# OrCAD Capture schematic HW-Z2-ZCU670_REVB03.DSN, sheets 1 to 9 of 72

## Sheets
1 001 Title Page
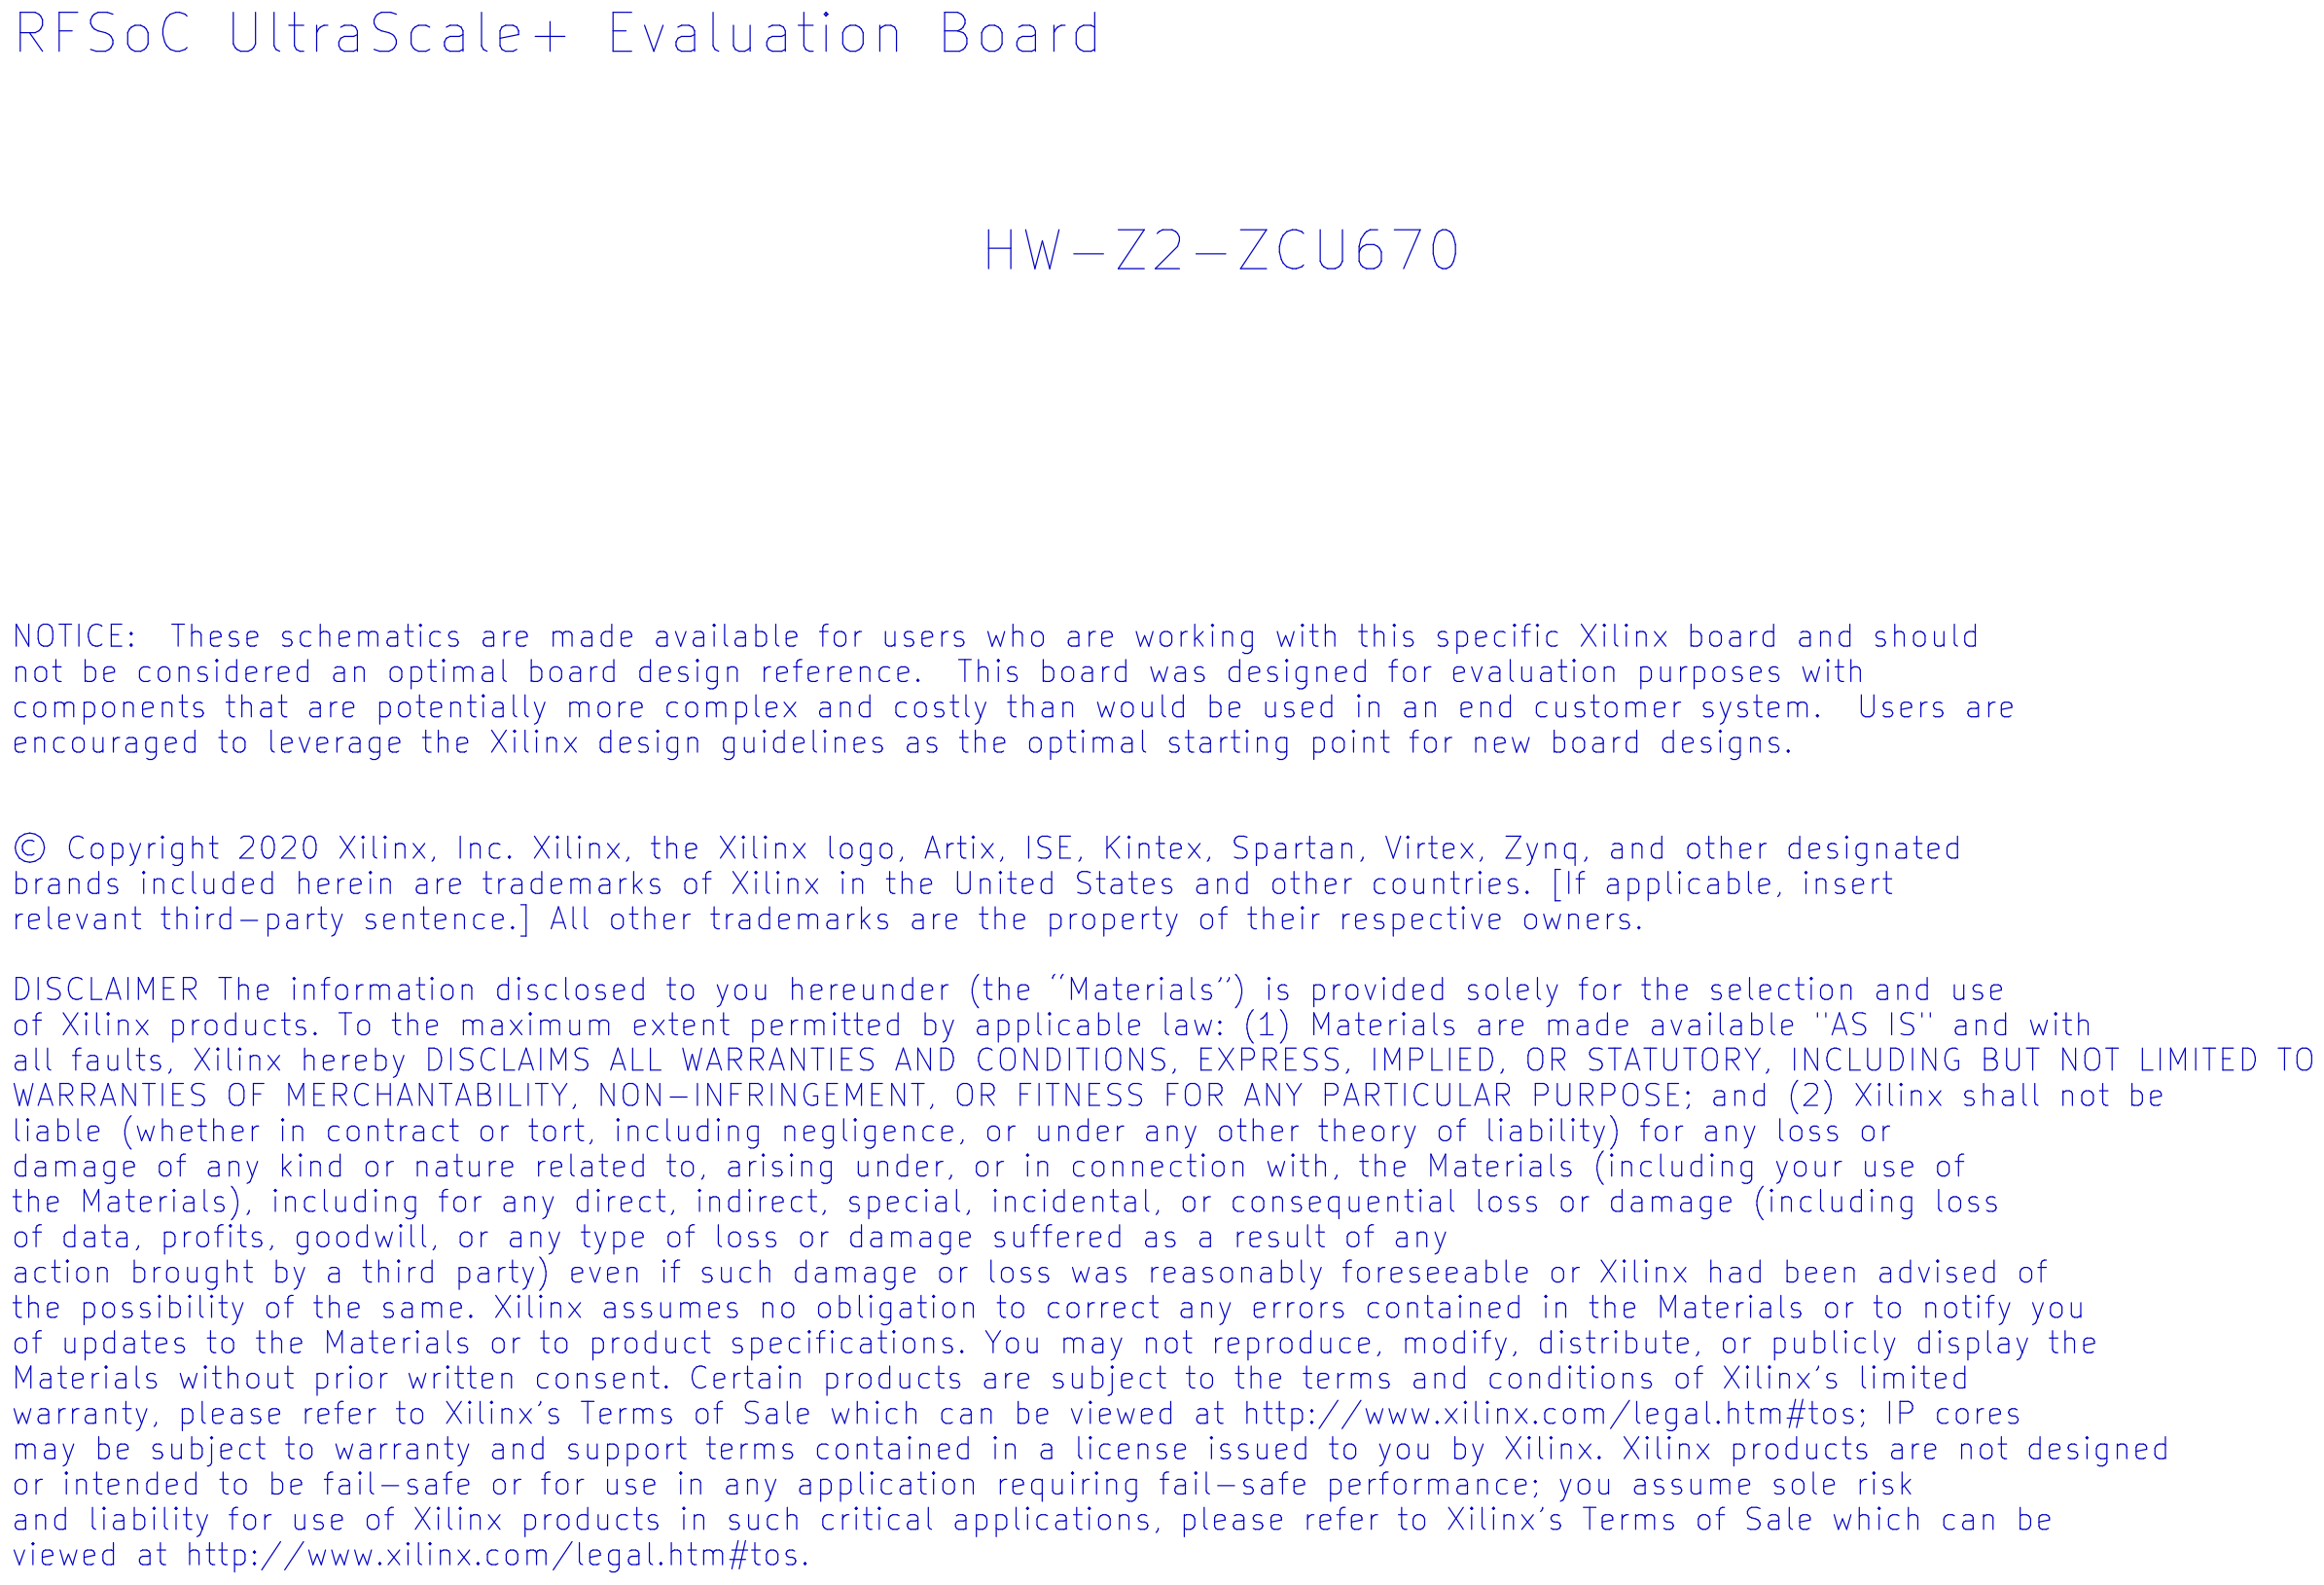
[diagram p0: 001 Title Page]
2 002 Block Diagram
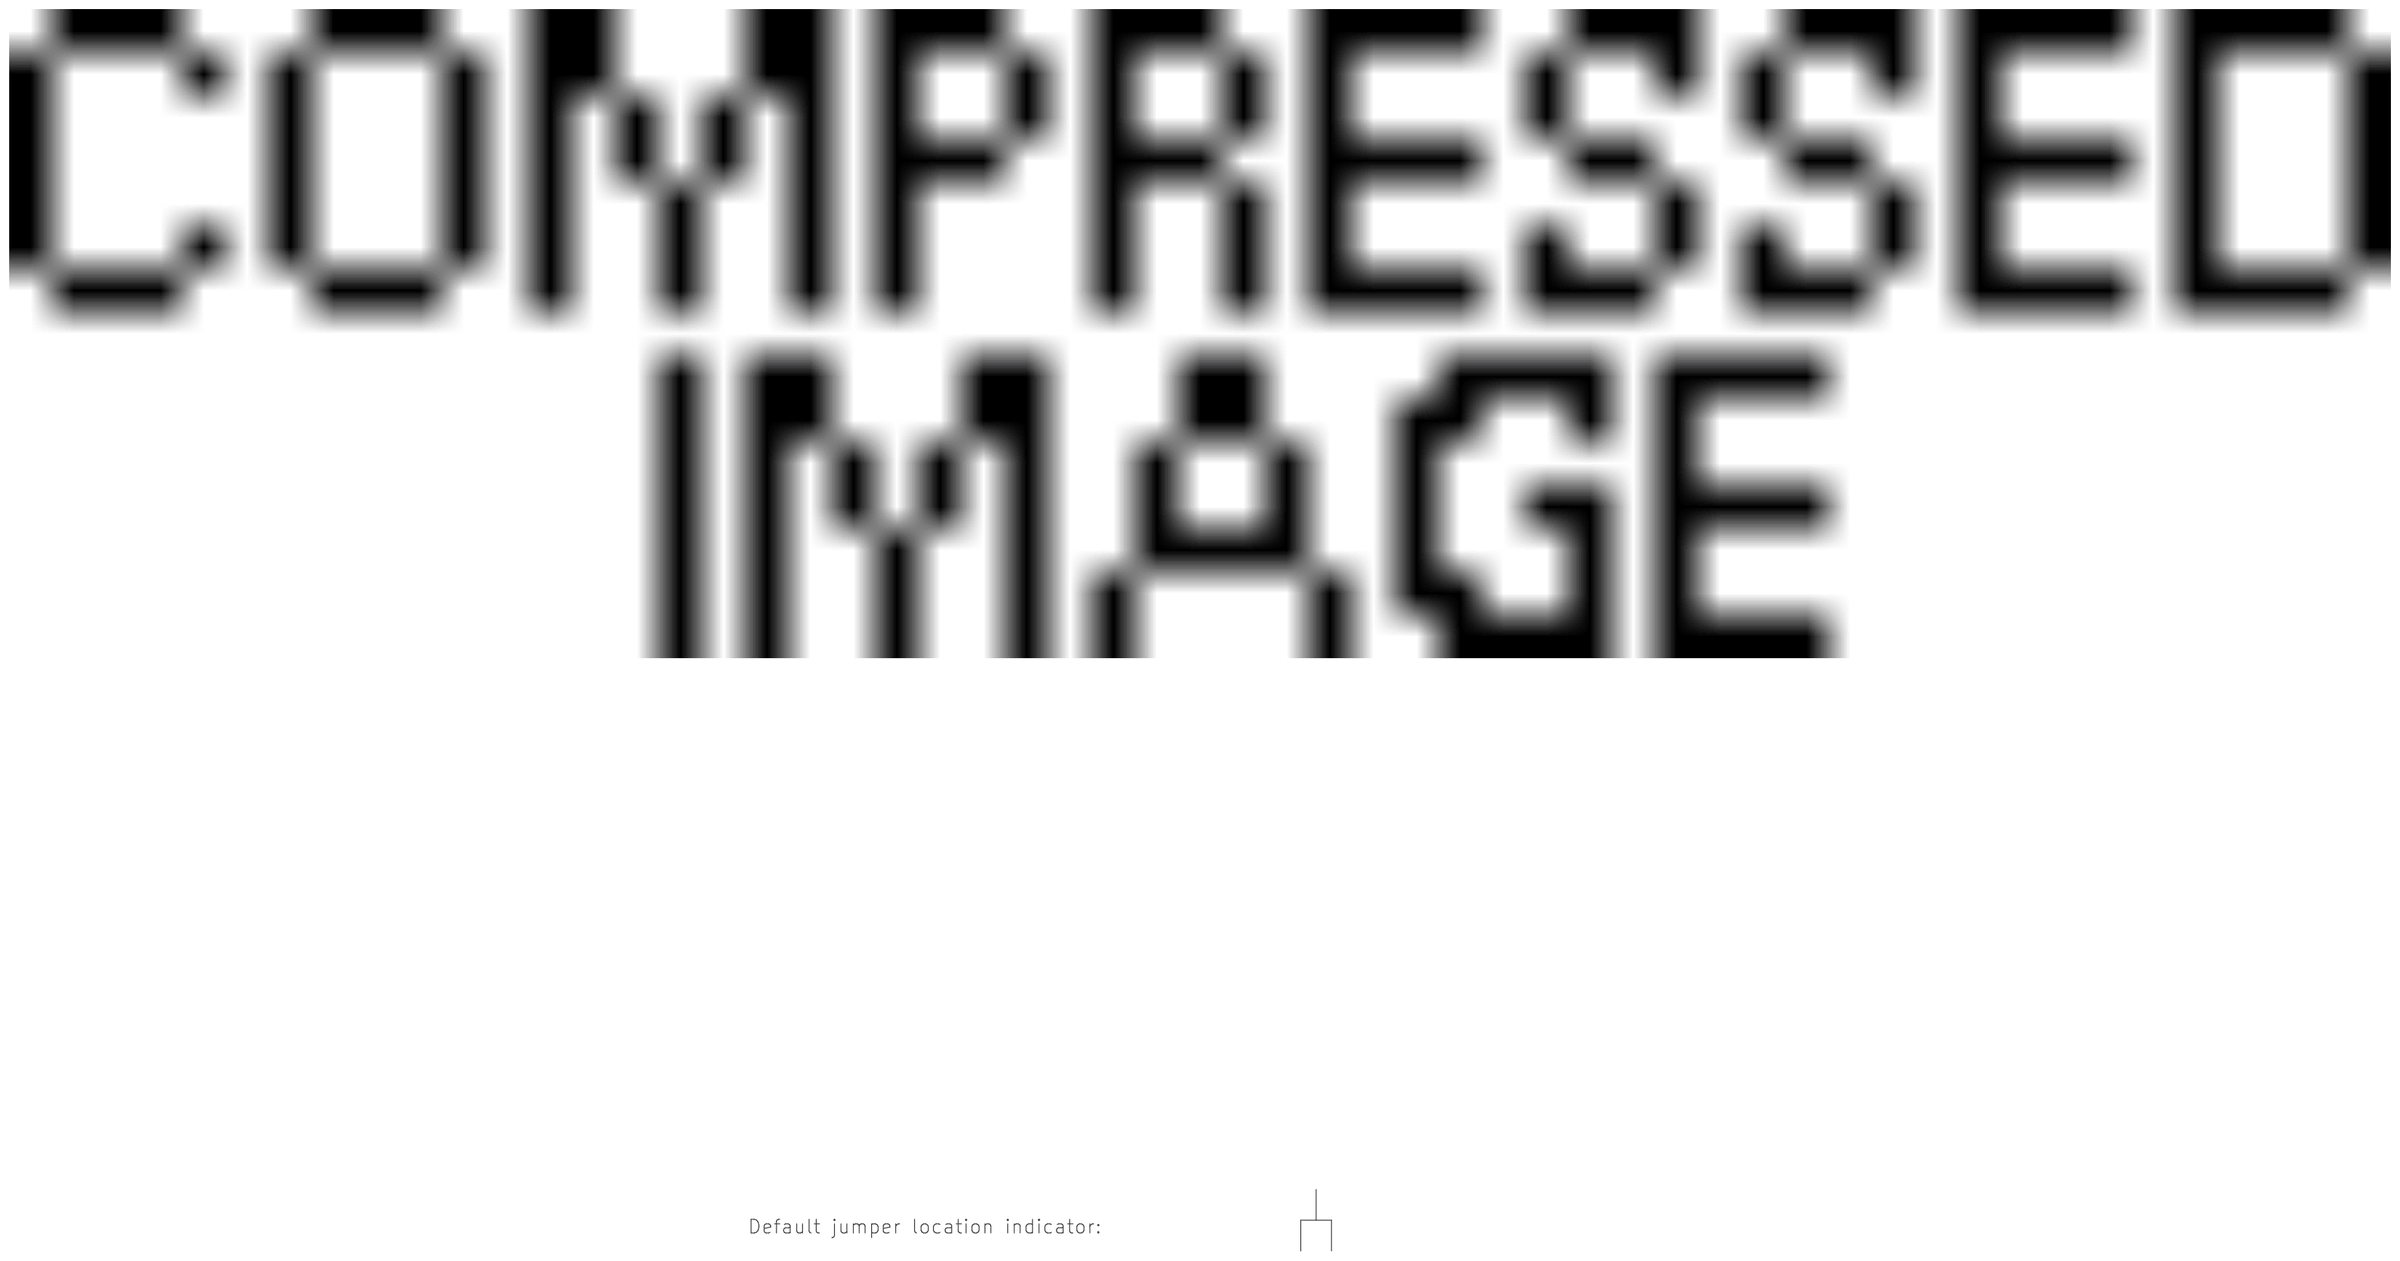
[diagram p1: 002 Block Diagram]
3 003 Zynq Bank 0: size Custom
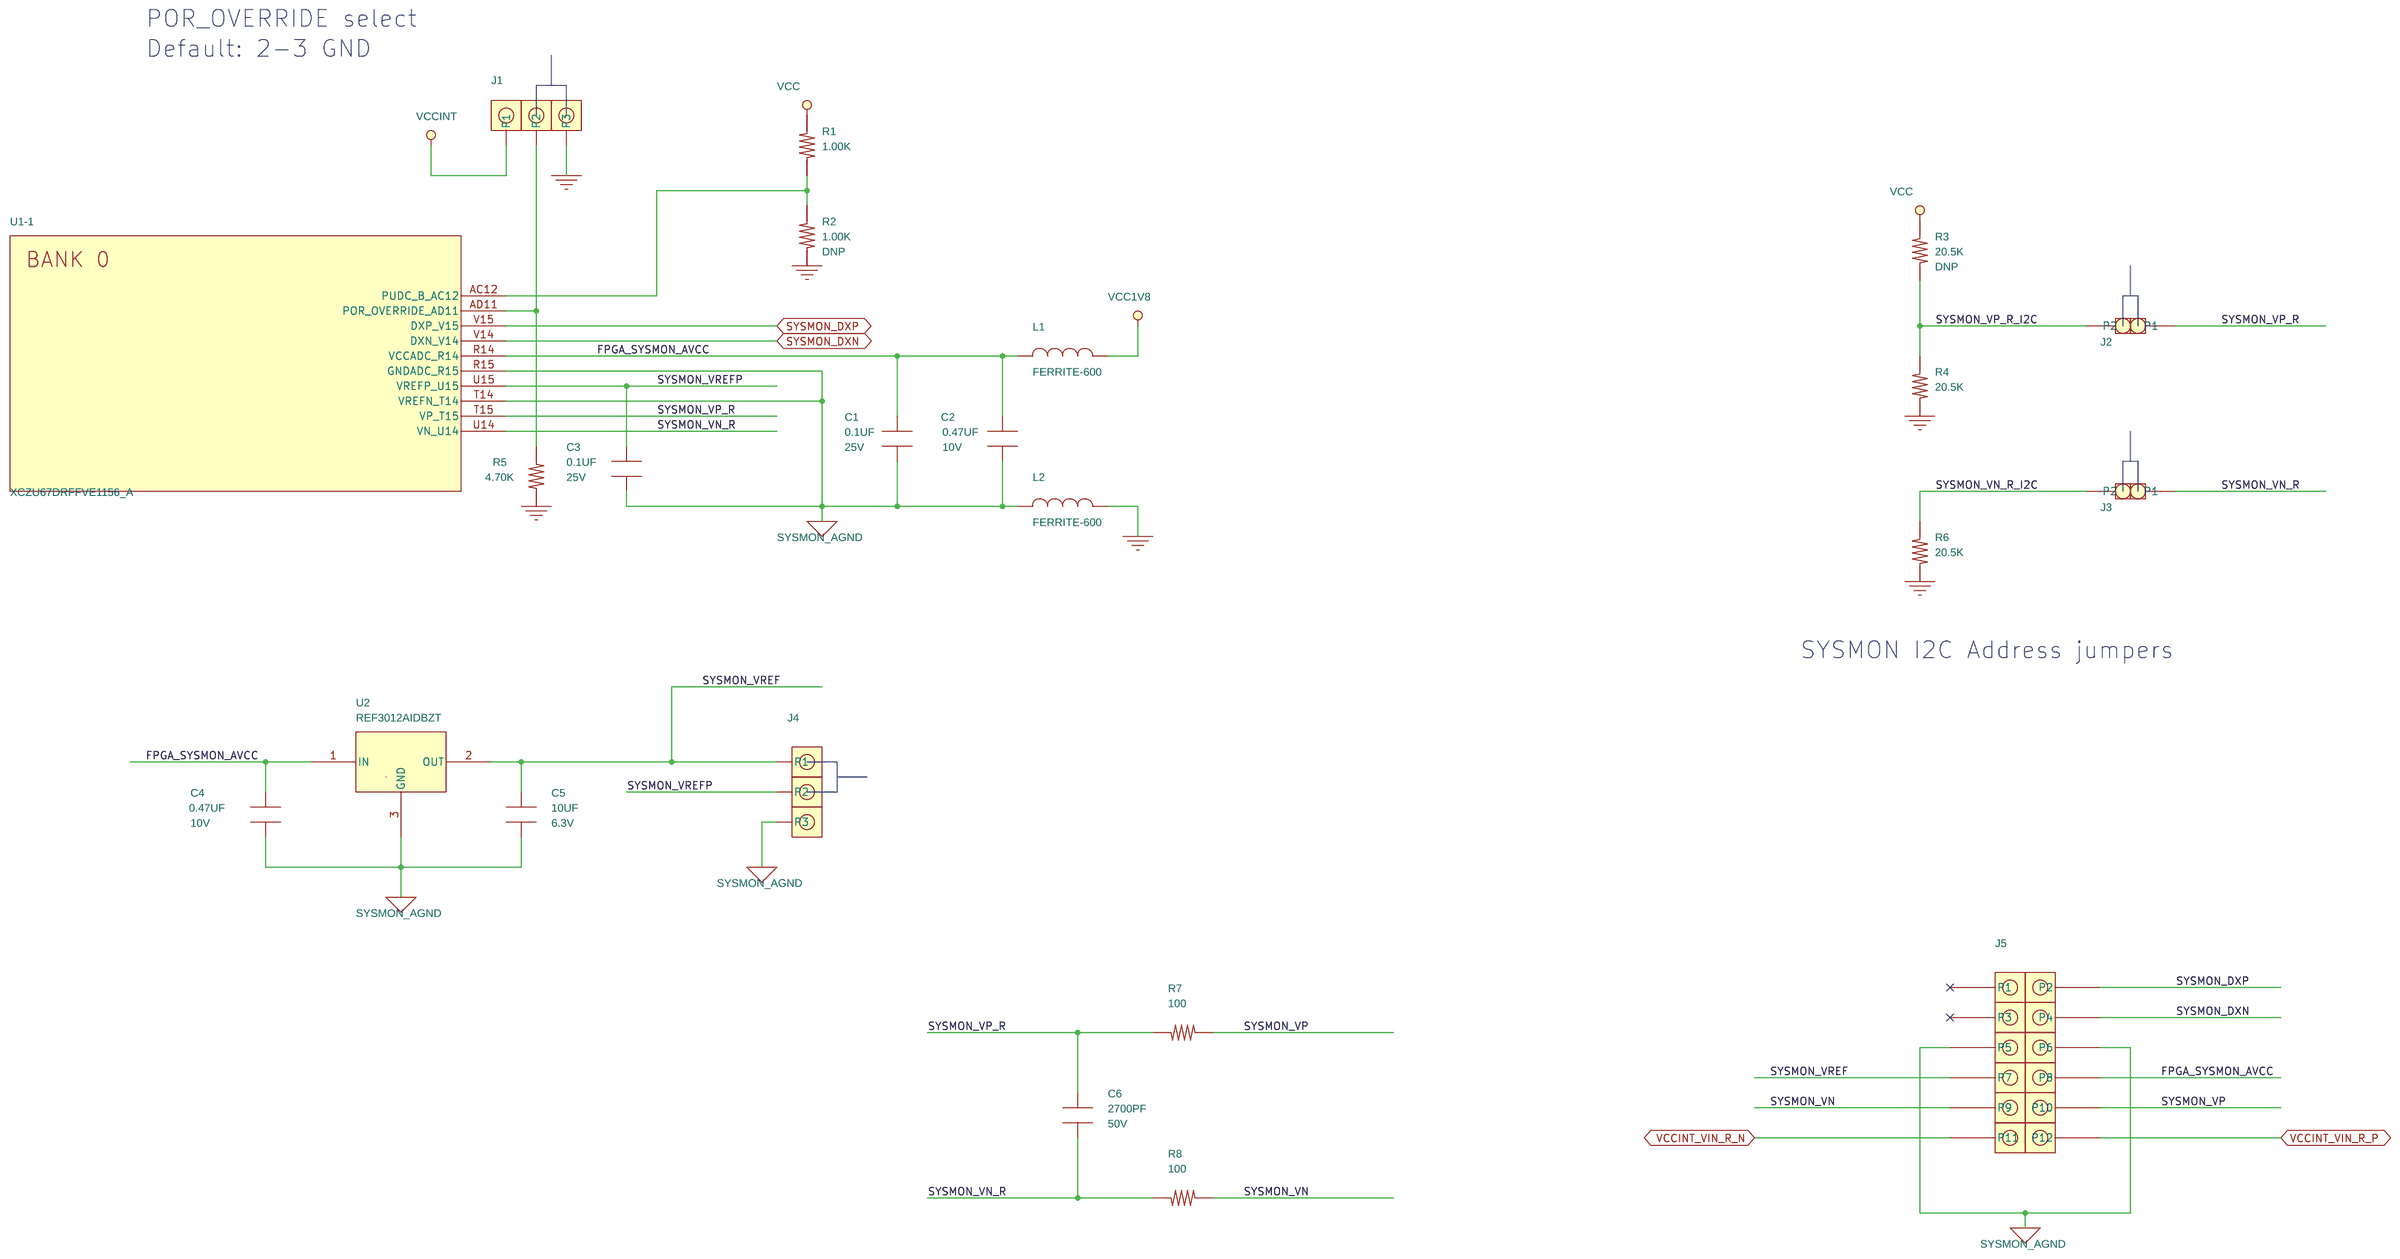
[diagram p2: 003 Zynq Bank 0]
4 004 Zynq Bank 65 66: size Custom
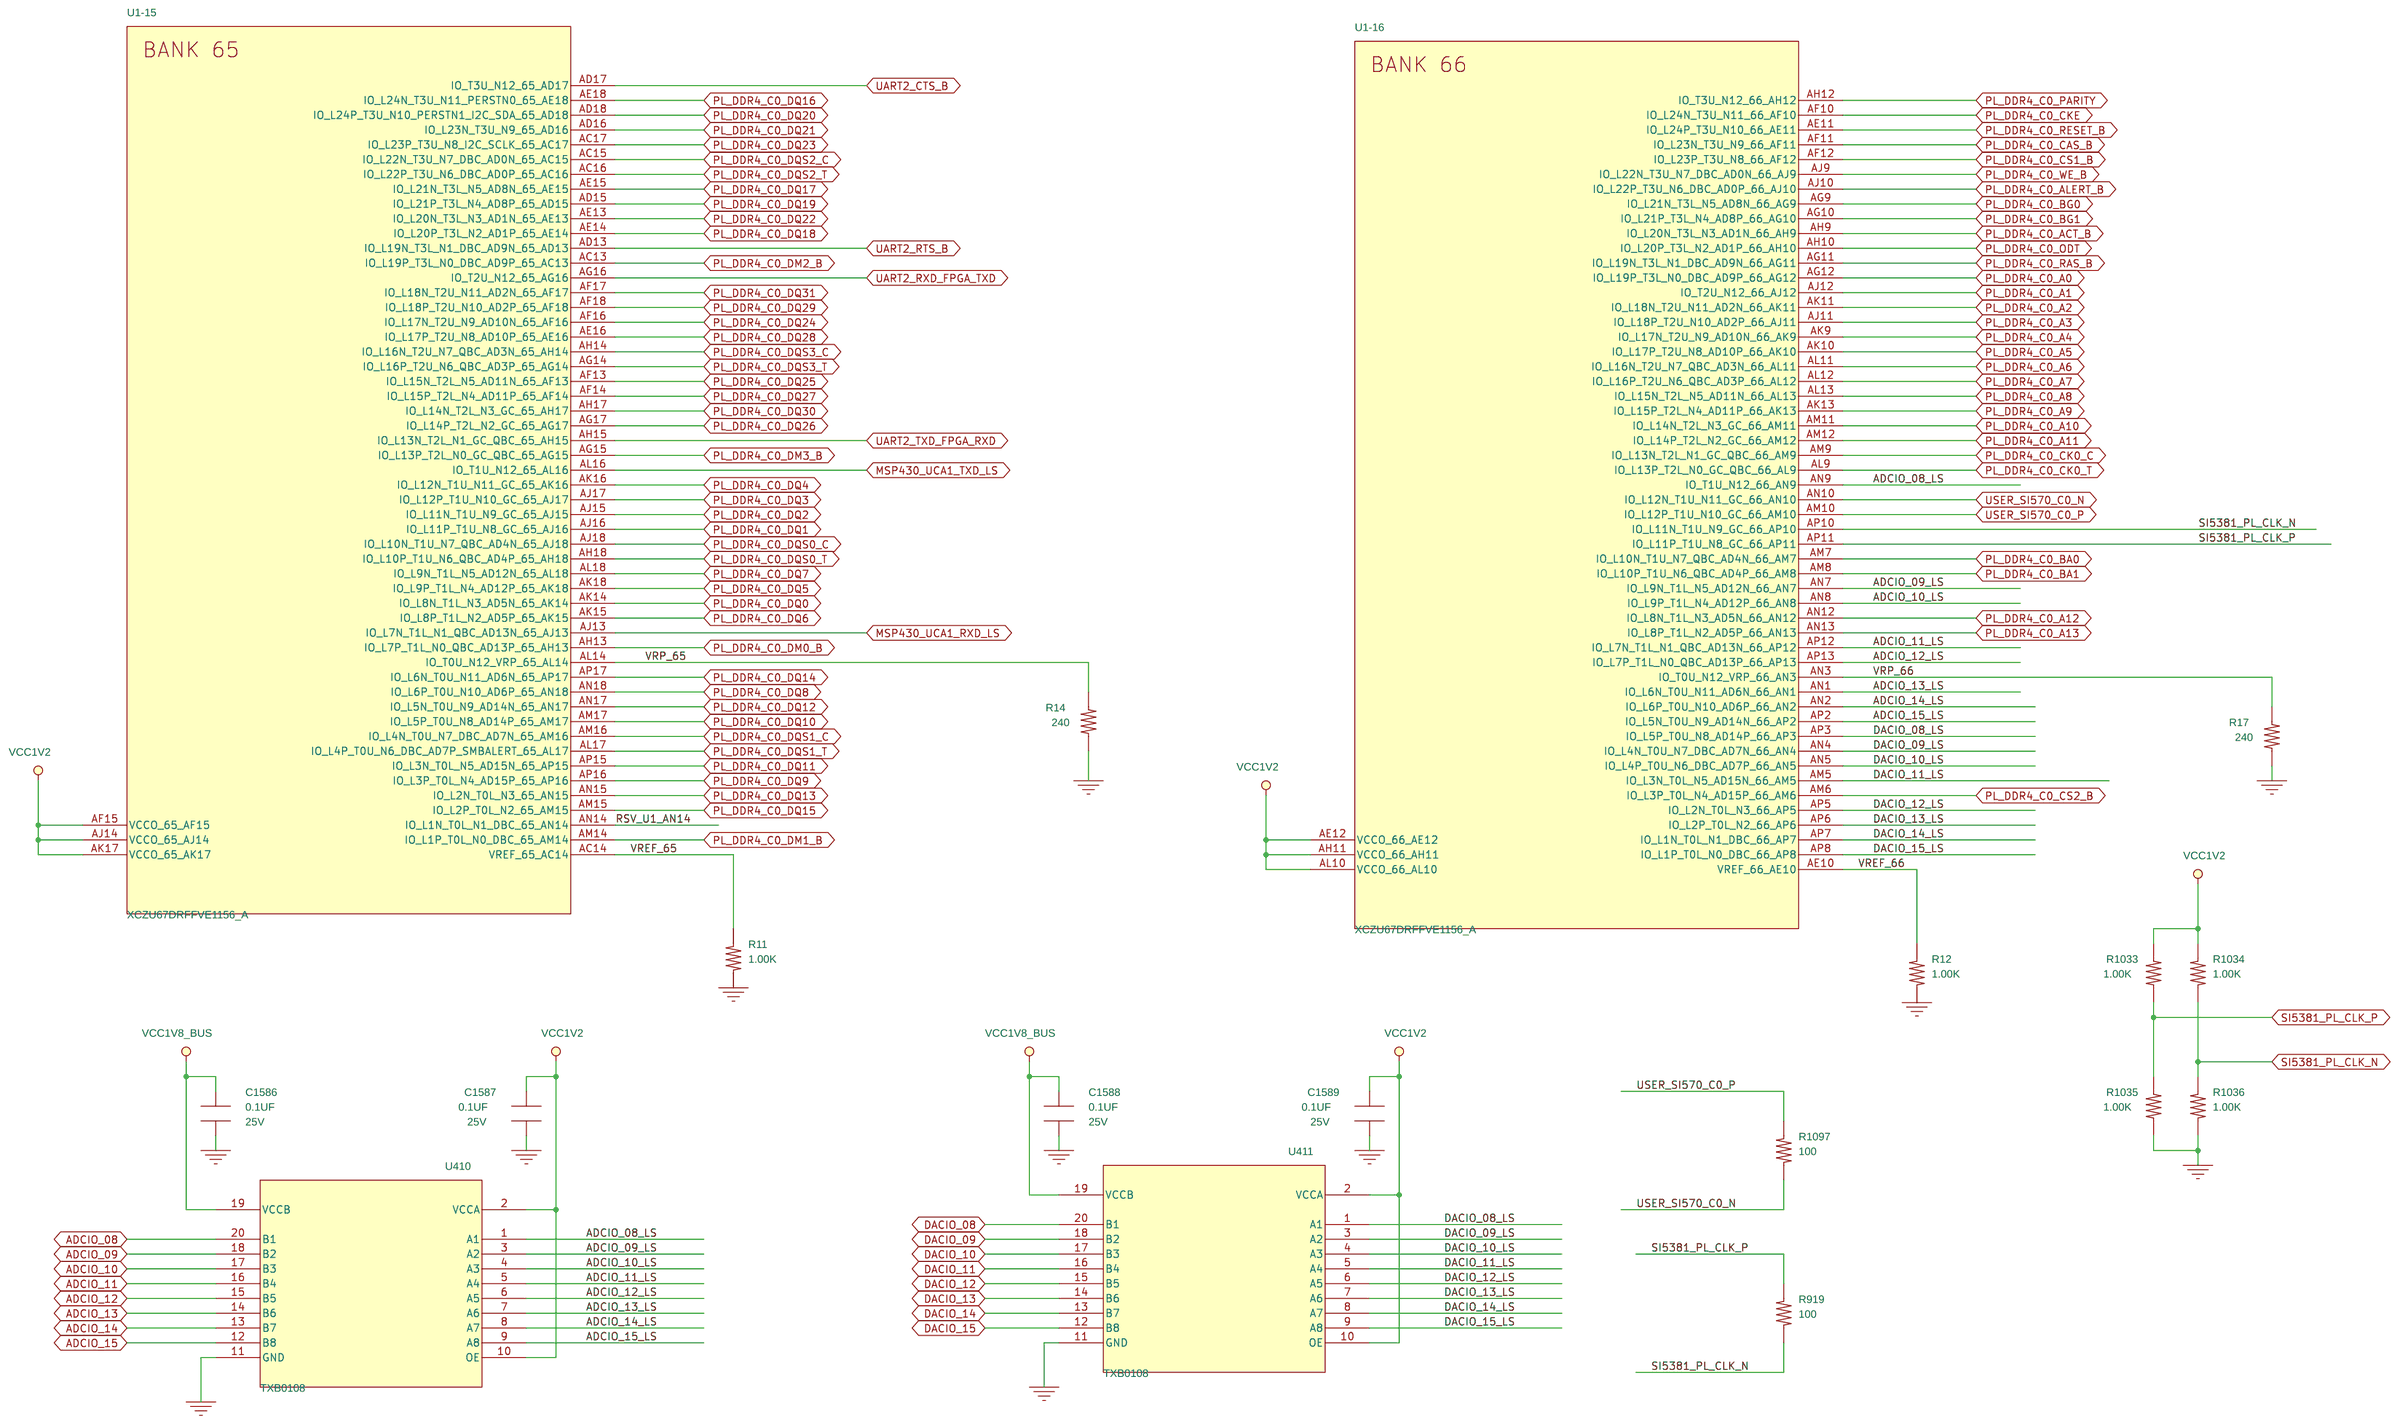
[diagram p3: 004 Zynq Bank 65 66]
5 005 Zynq Bank 67 88: size Custom
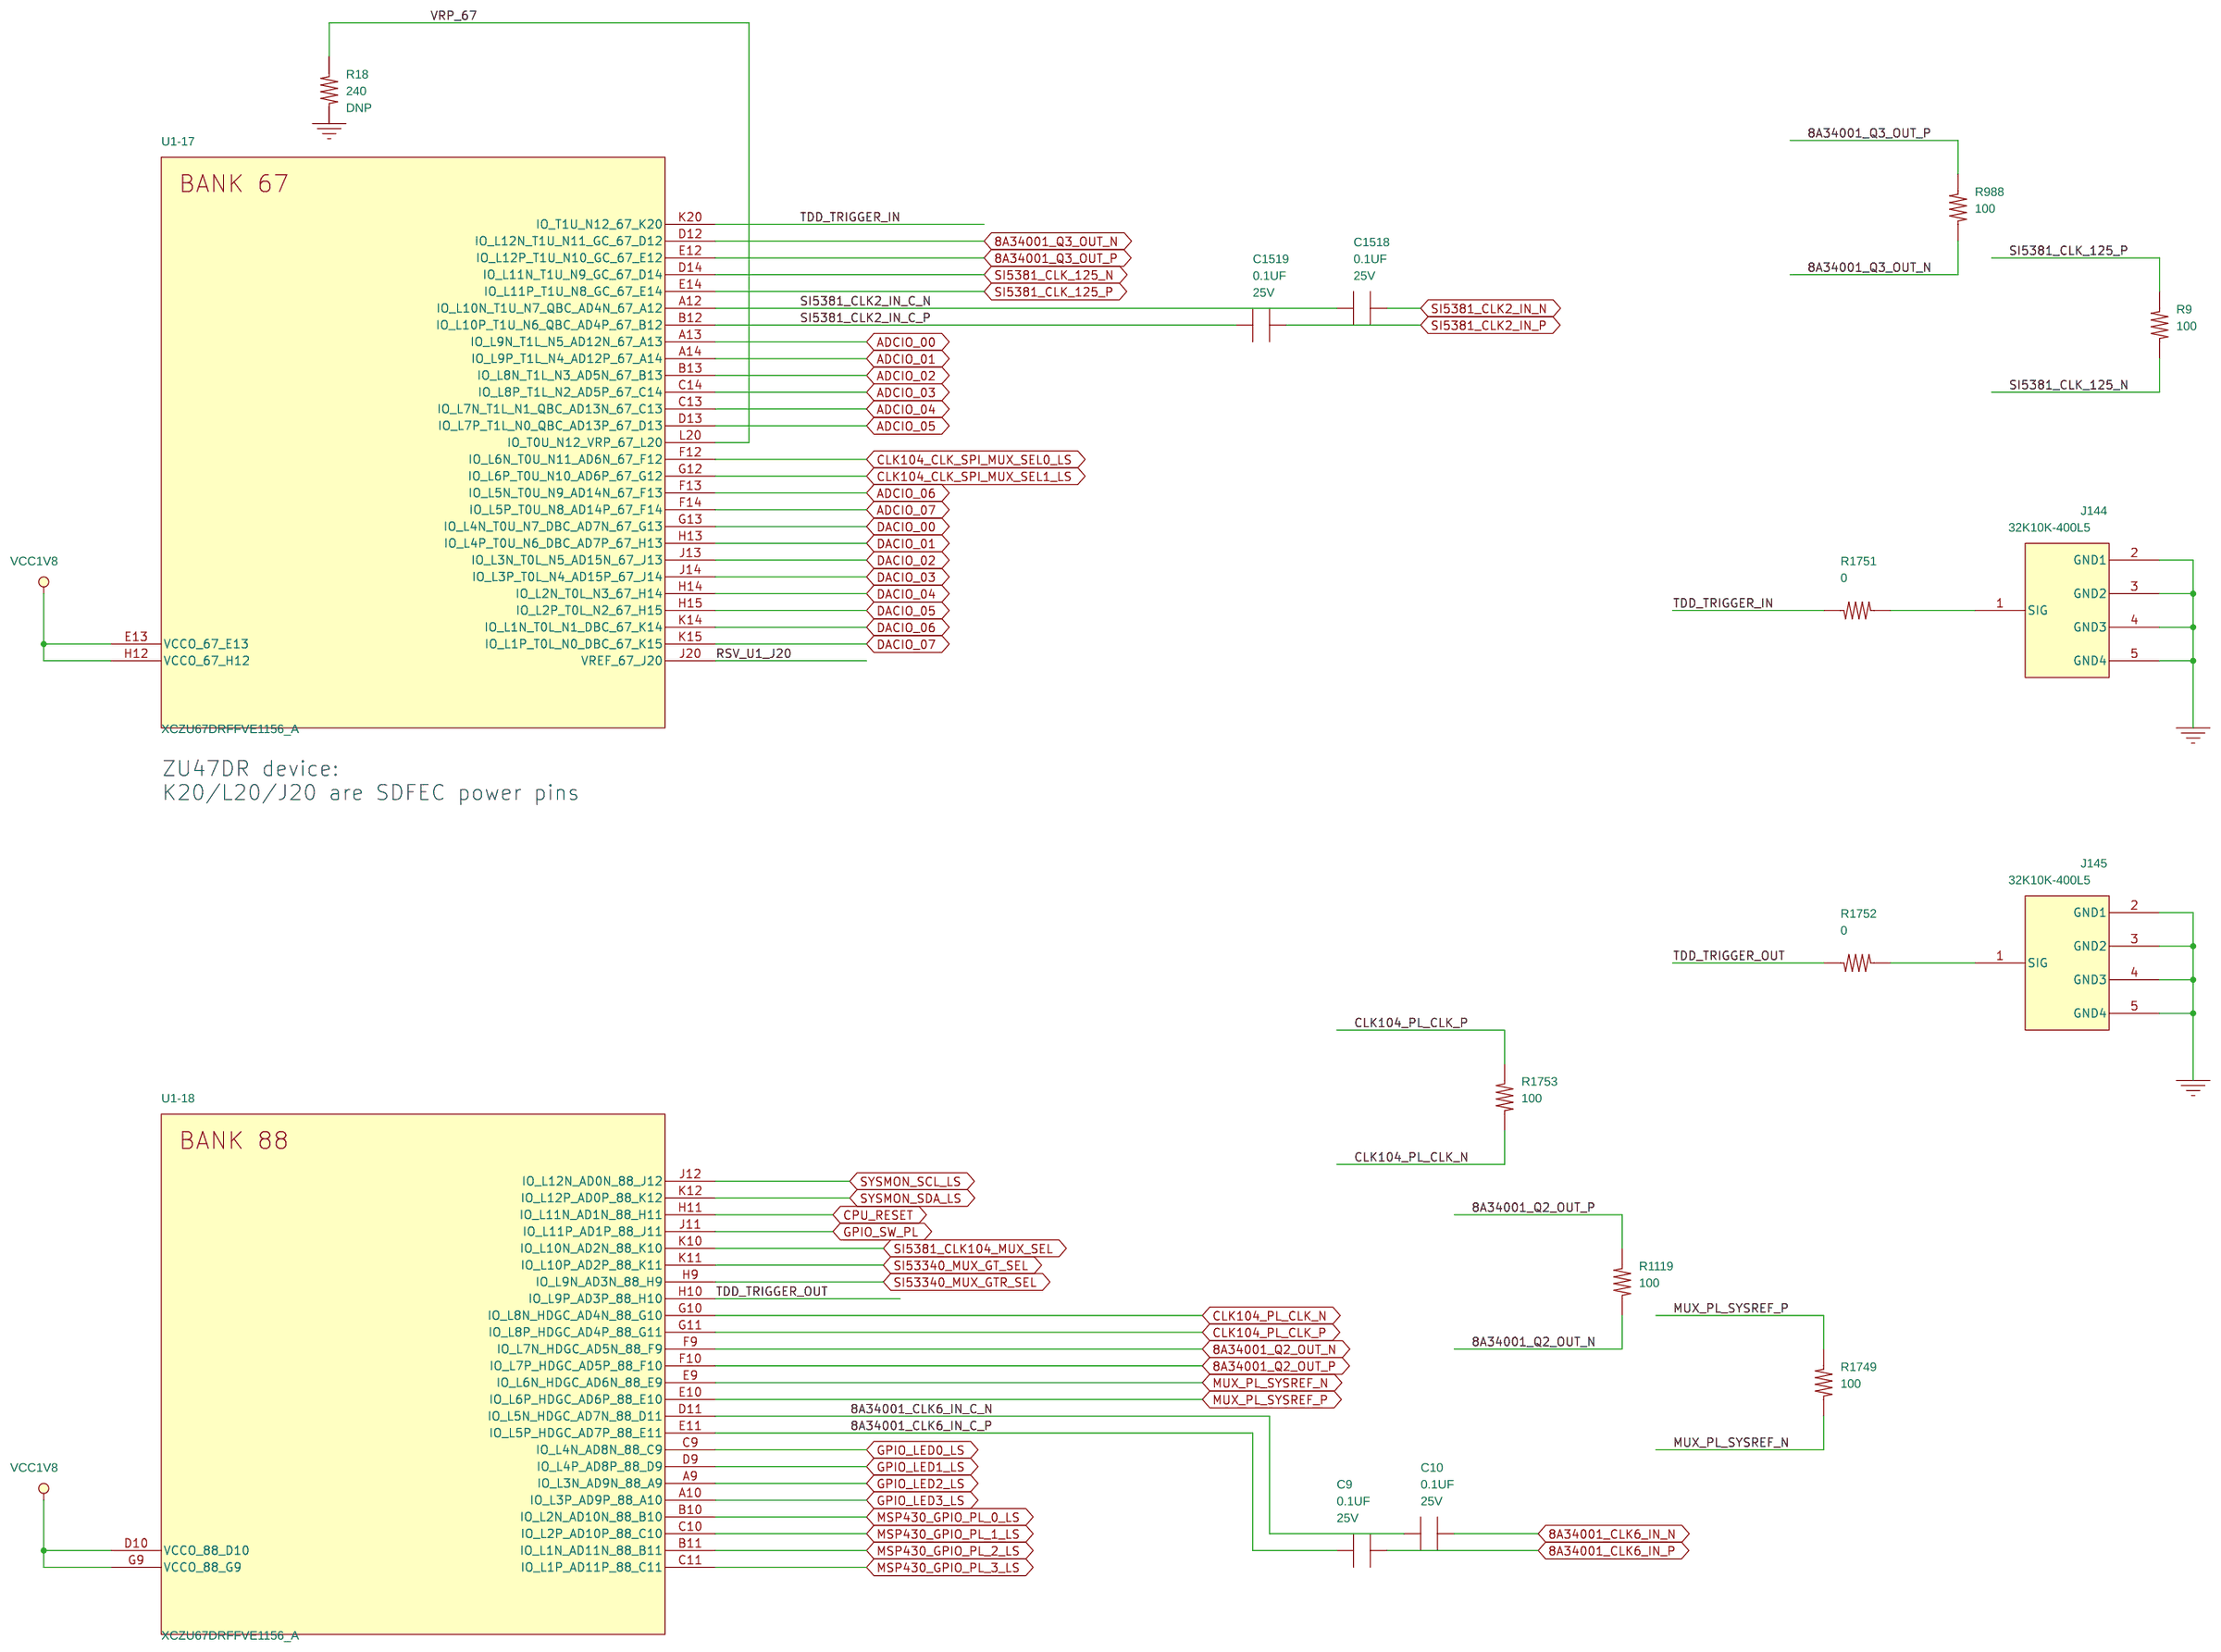
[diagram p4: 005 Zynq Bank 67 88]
6 006 Zynq Bank 127 128: size Custom
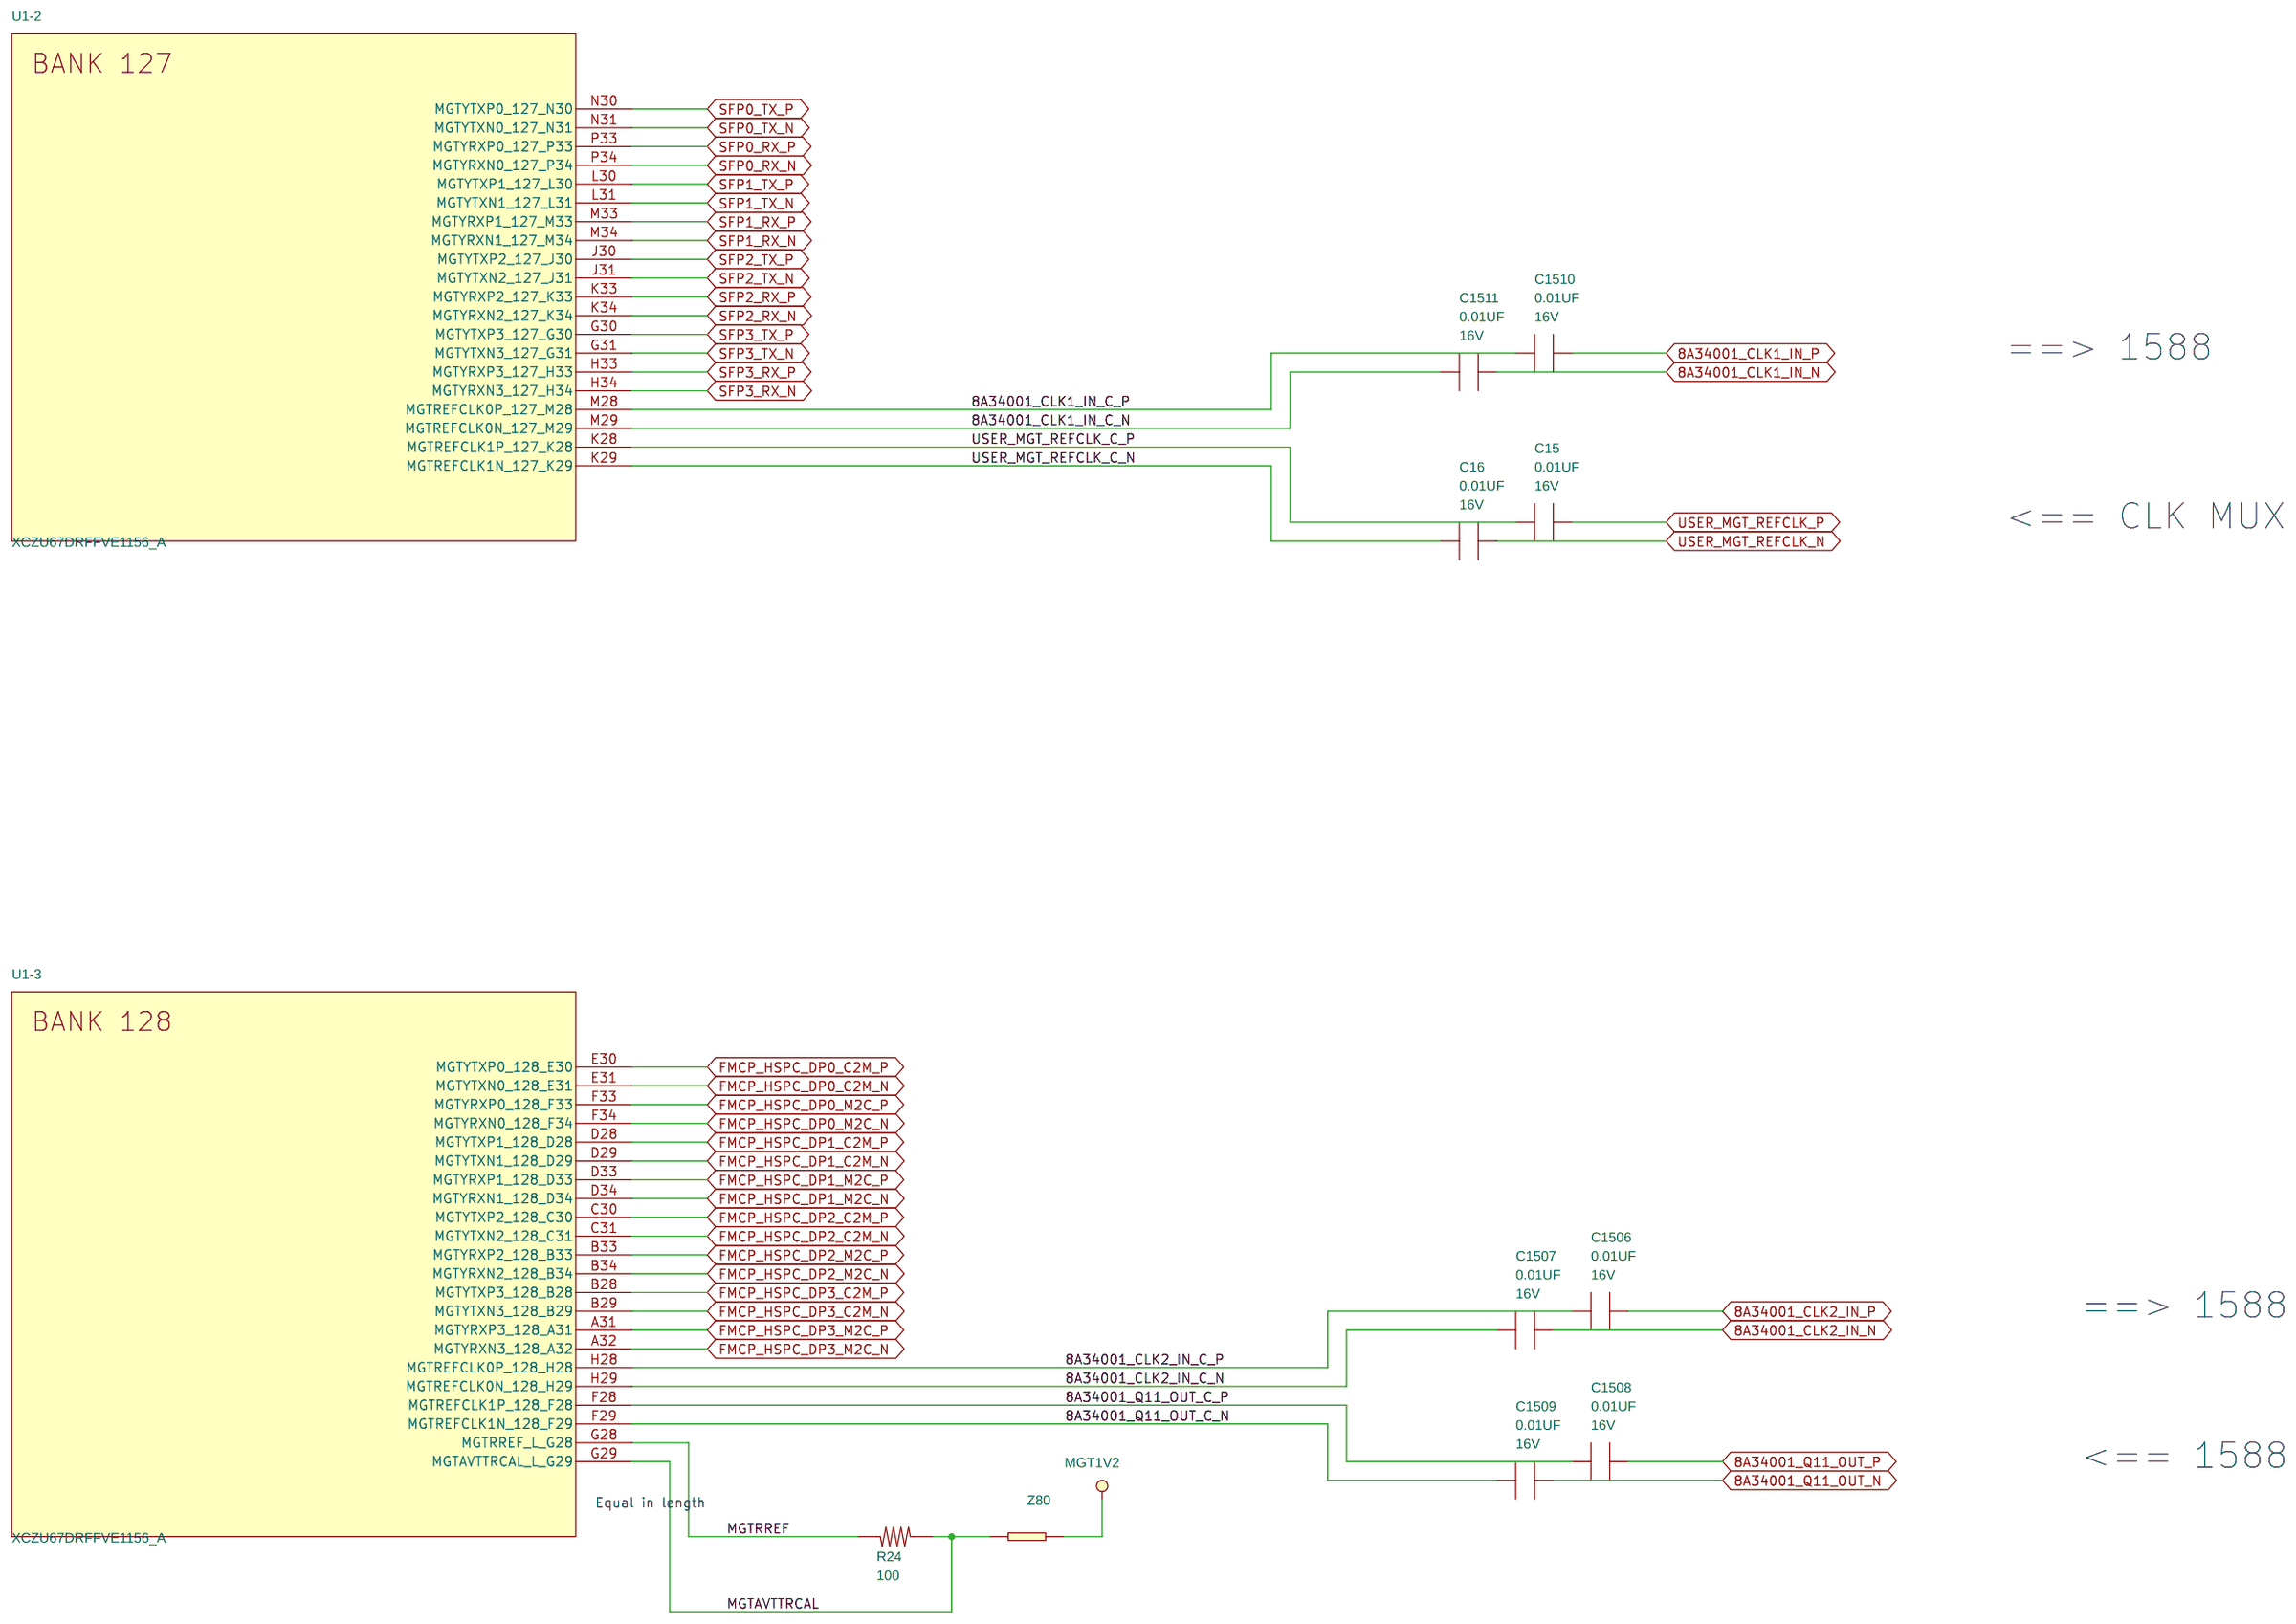
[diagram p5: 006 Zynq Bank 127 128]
7 007 Zynq Banks ADC: size Custom
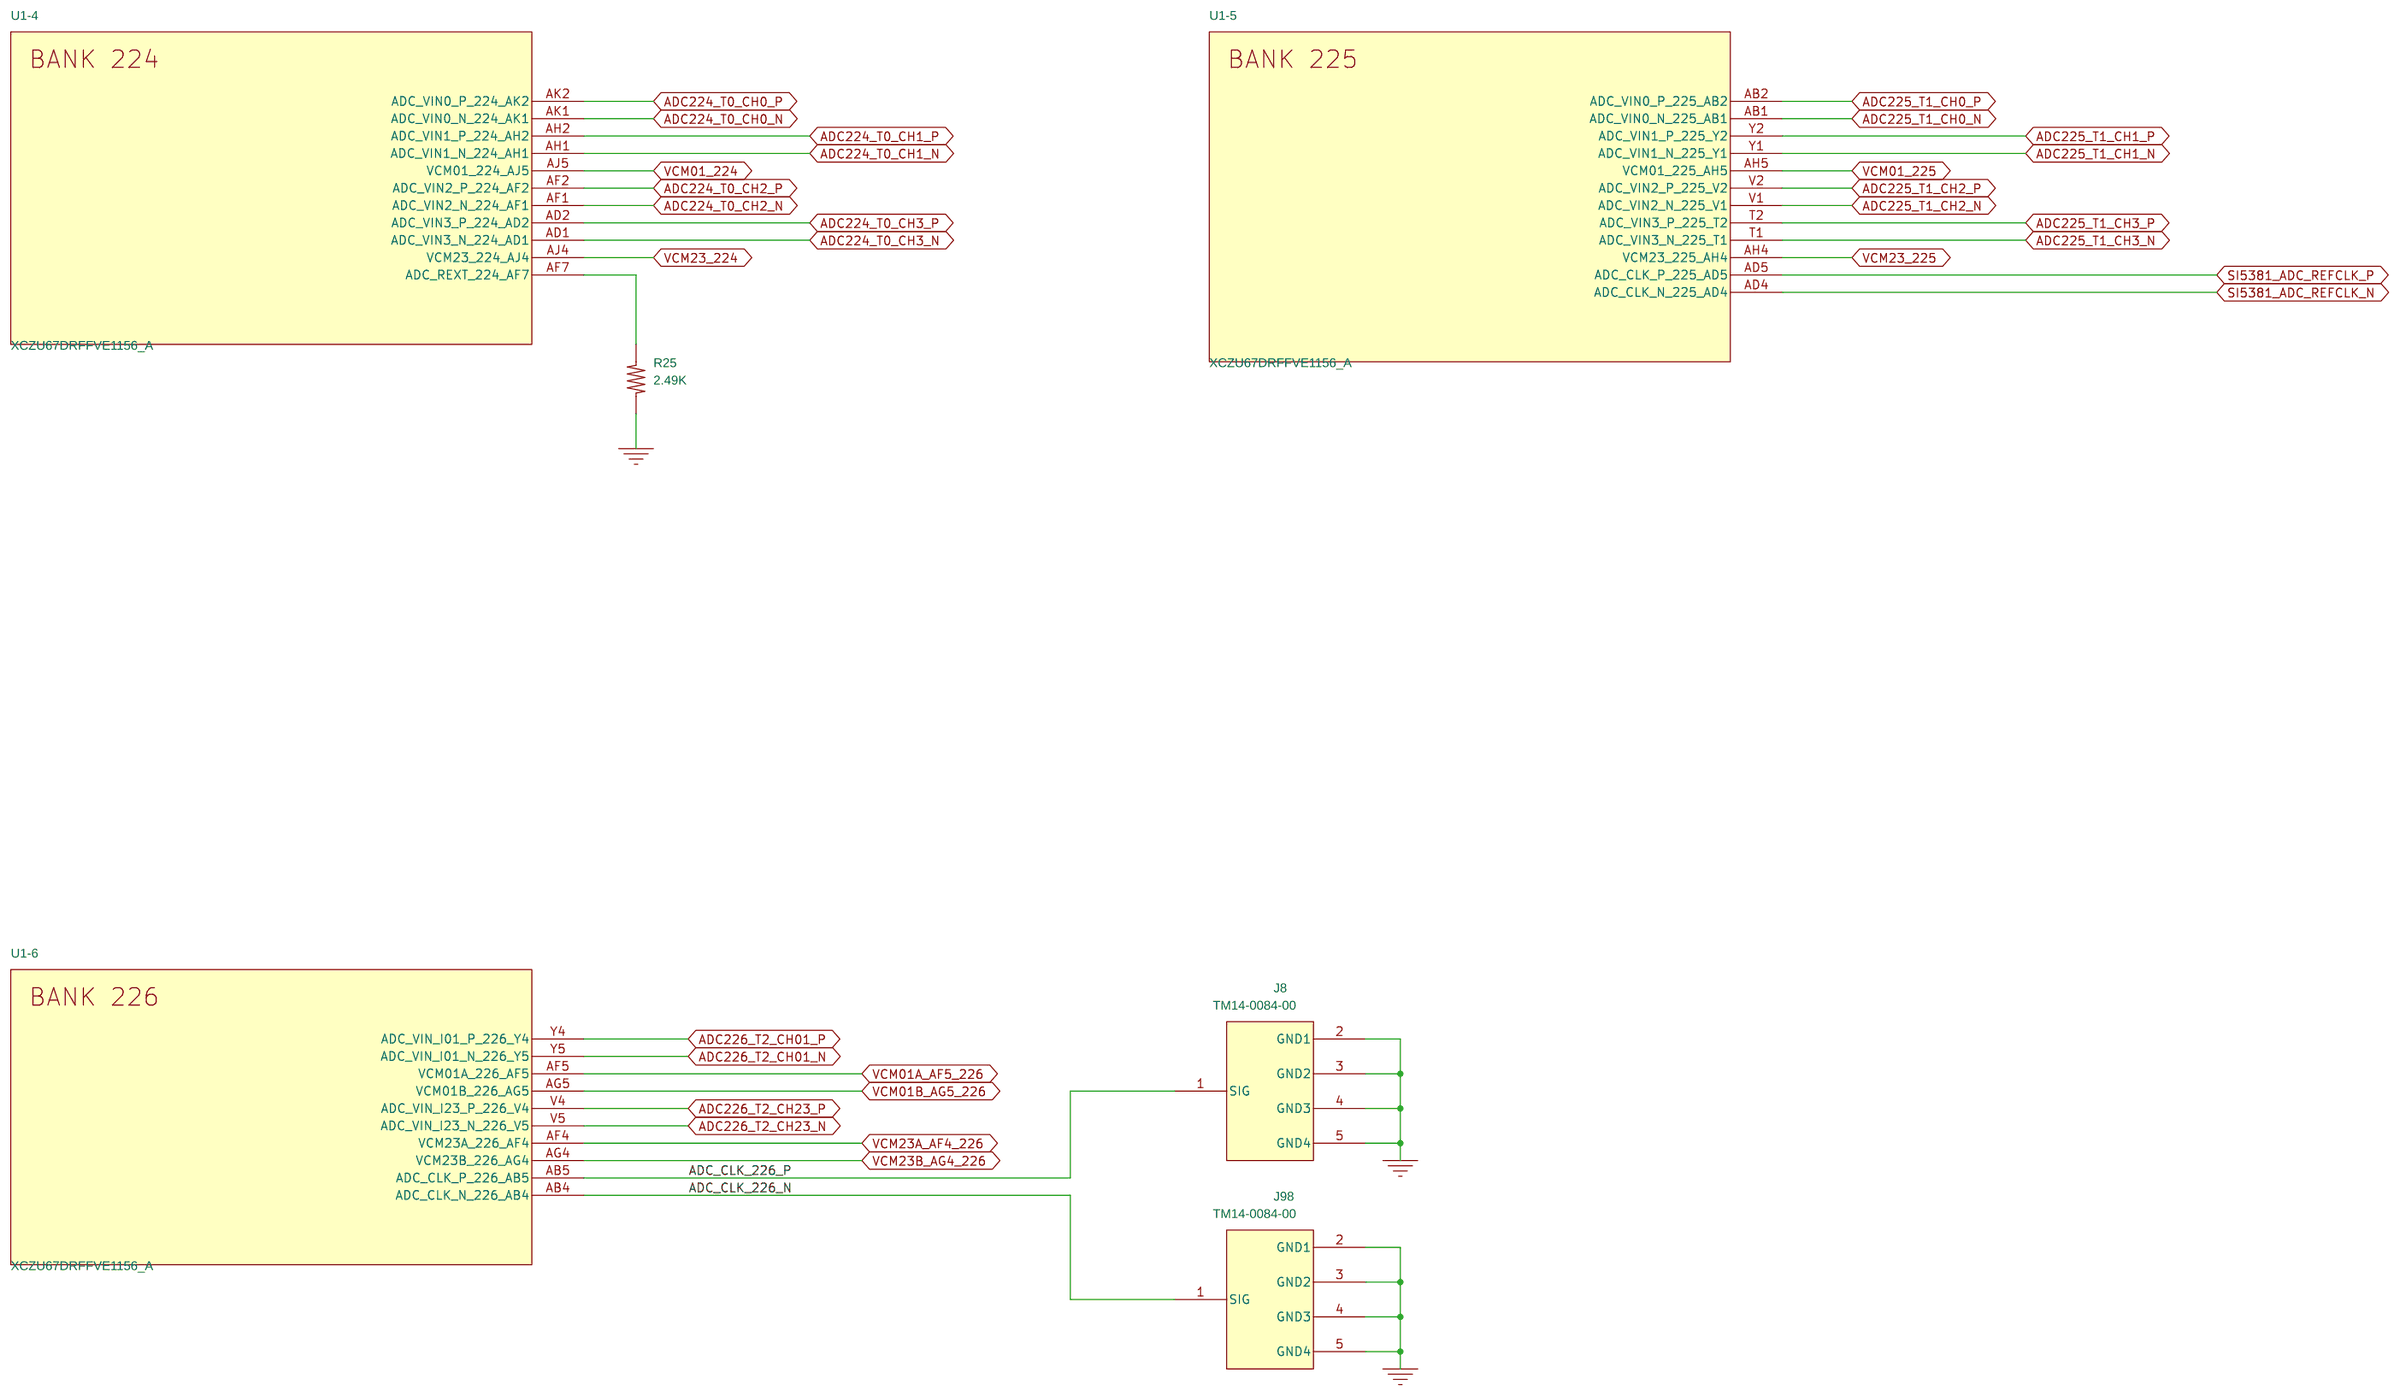
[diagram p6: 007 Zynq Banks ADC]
8 008 Zynq Banks DAC: size Custom
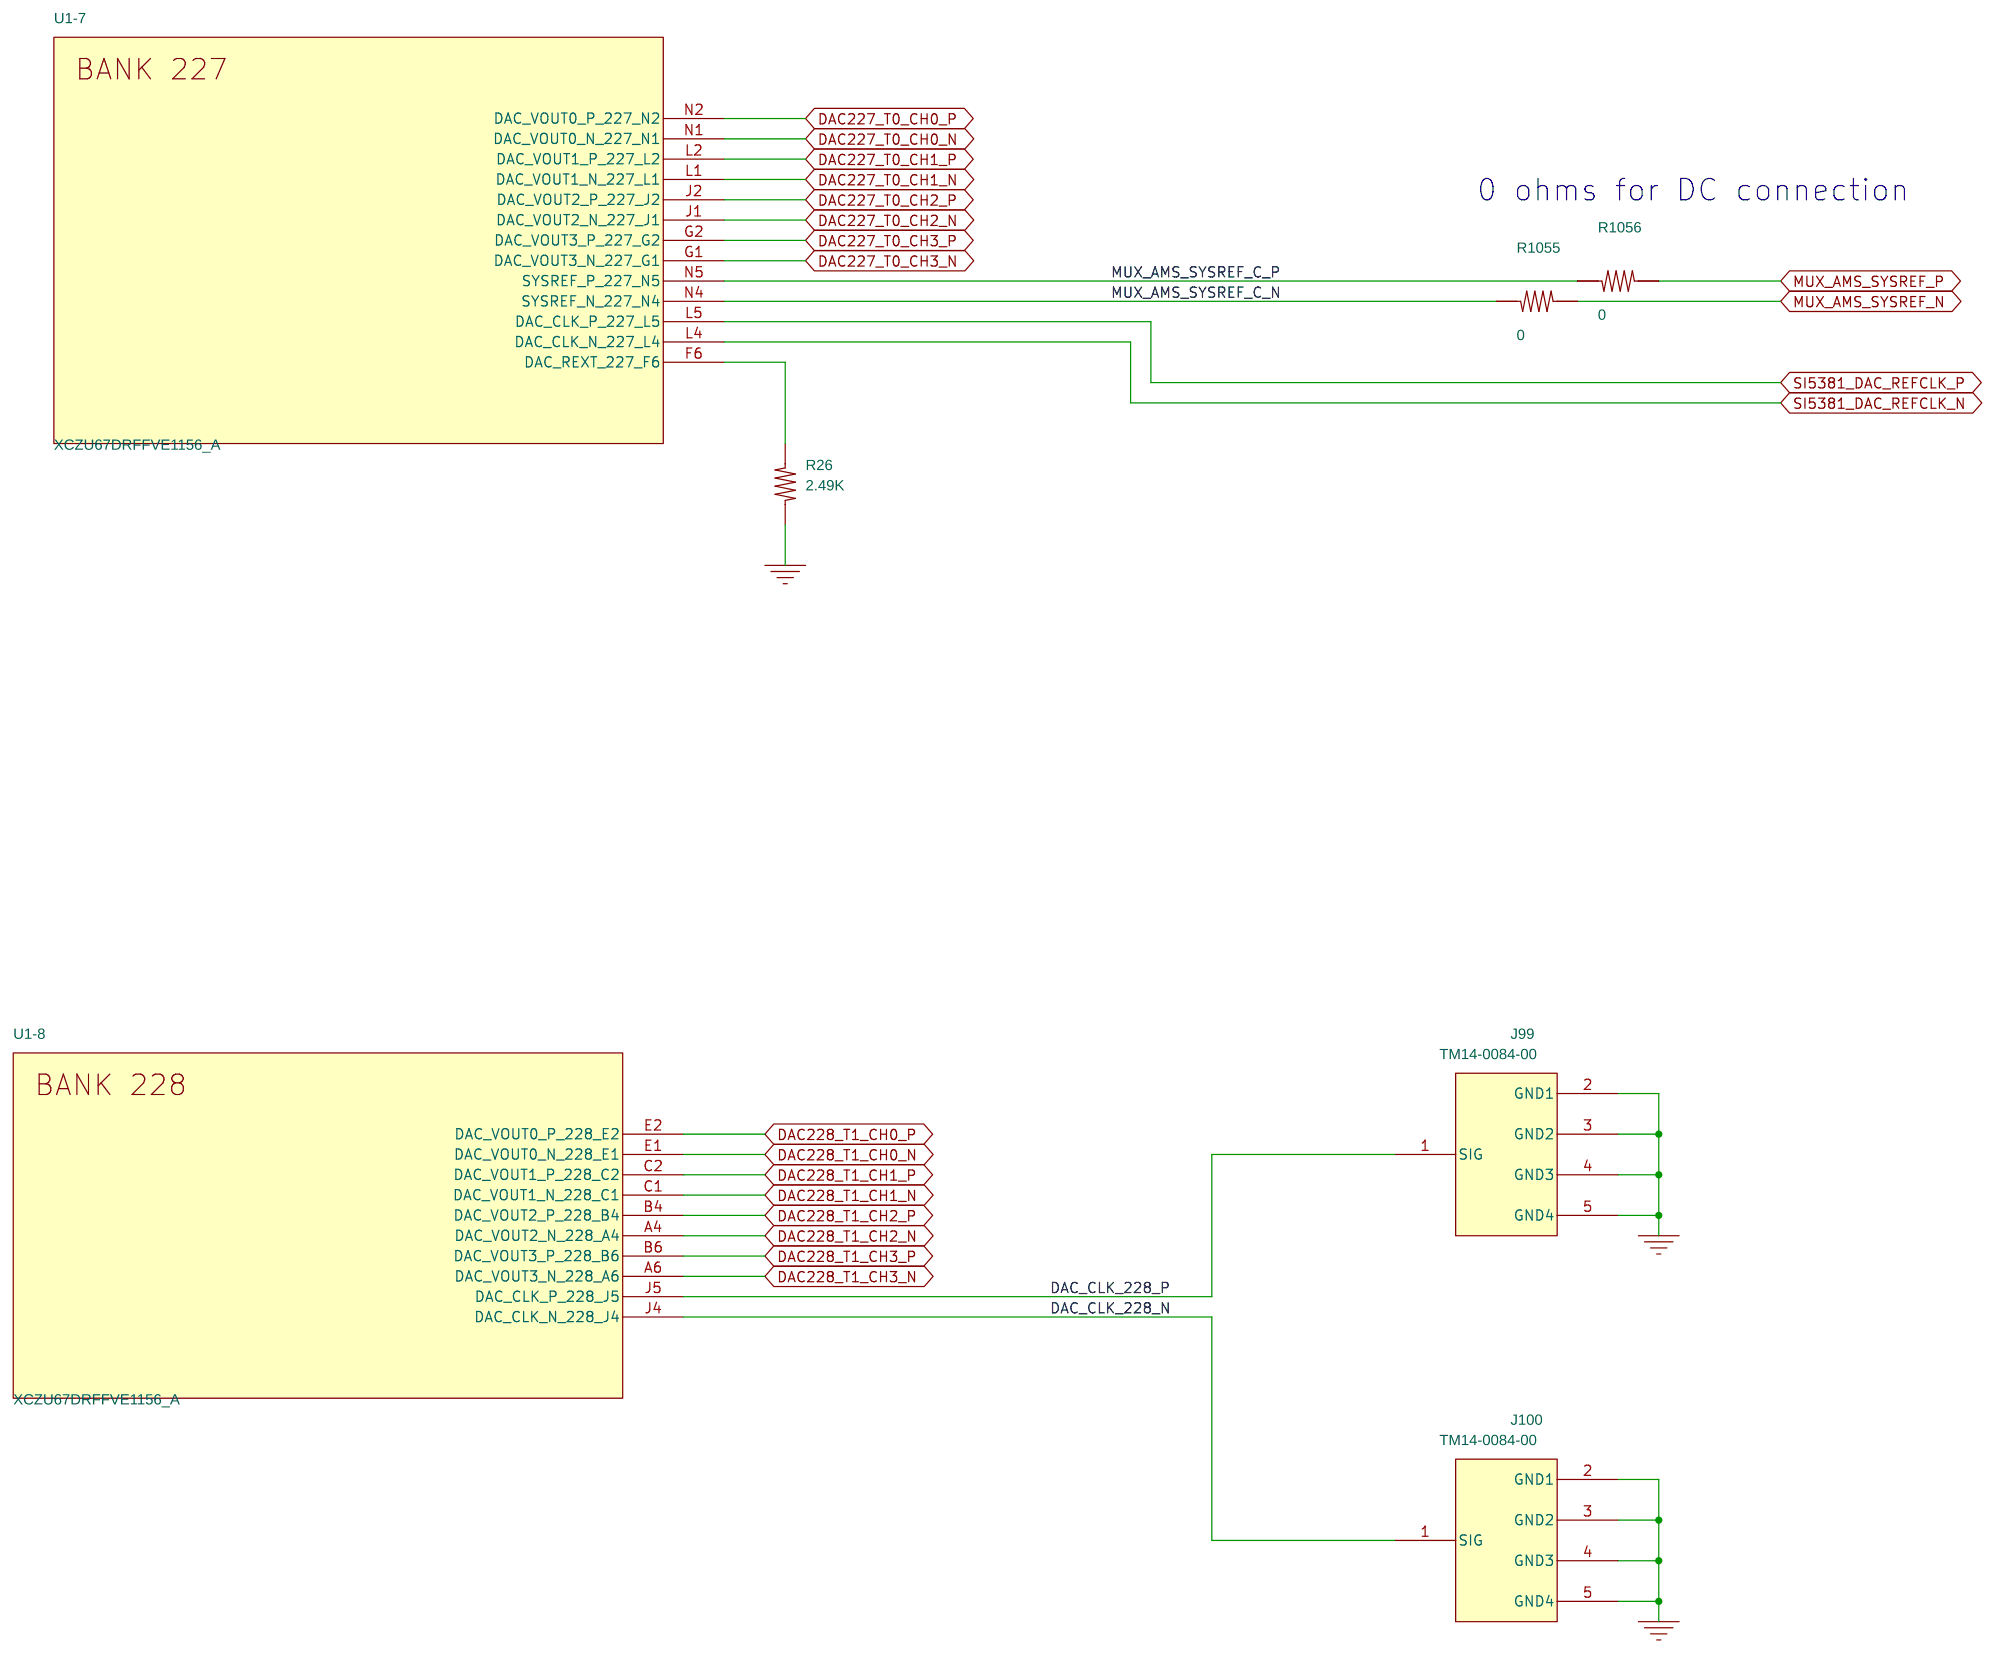
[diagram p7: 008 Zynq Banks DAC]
9 009 Zynq Bank 500 501 502 - MIO: size Custom
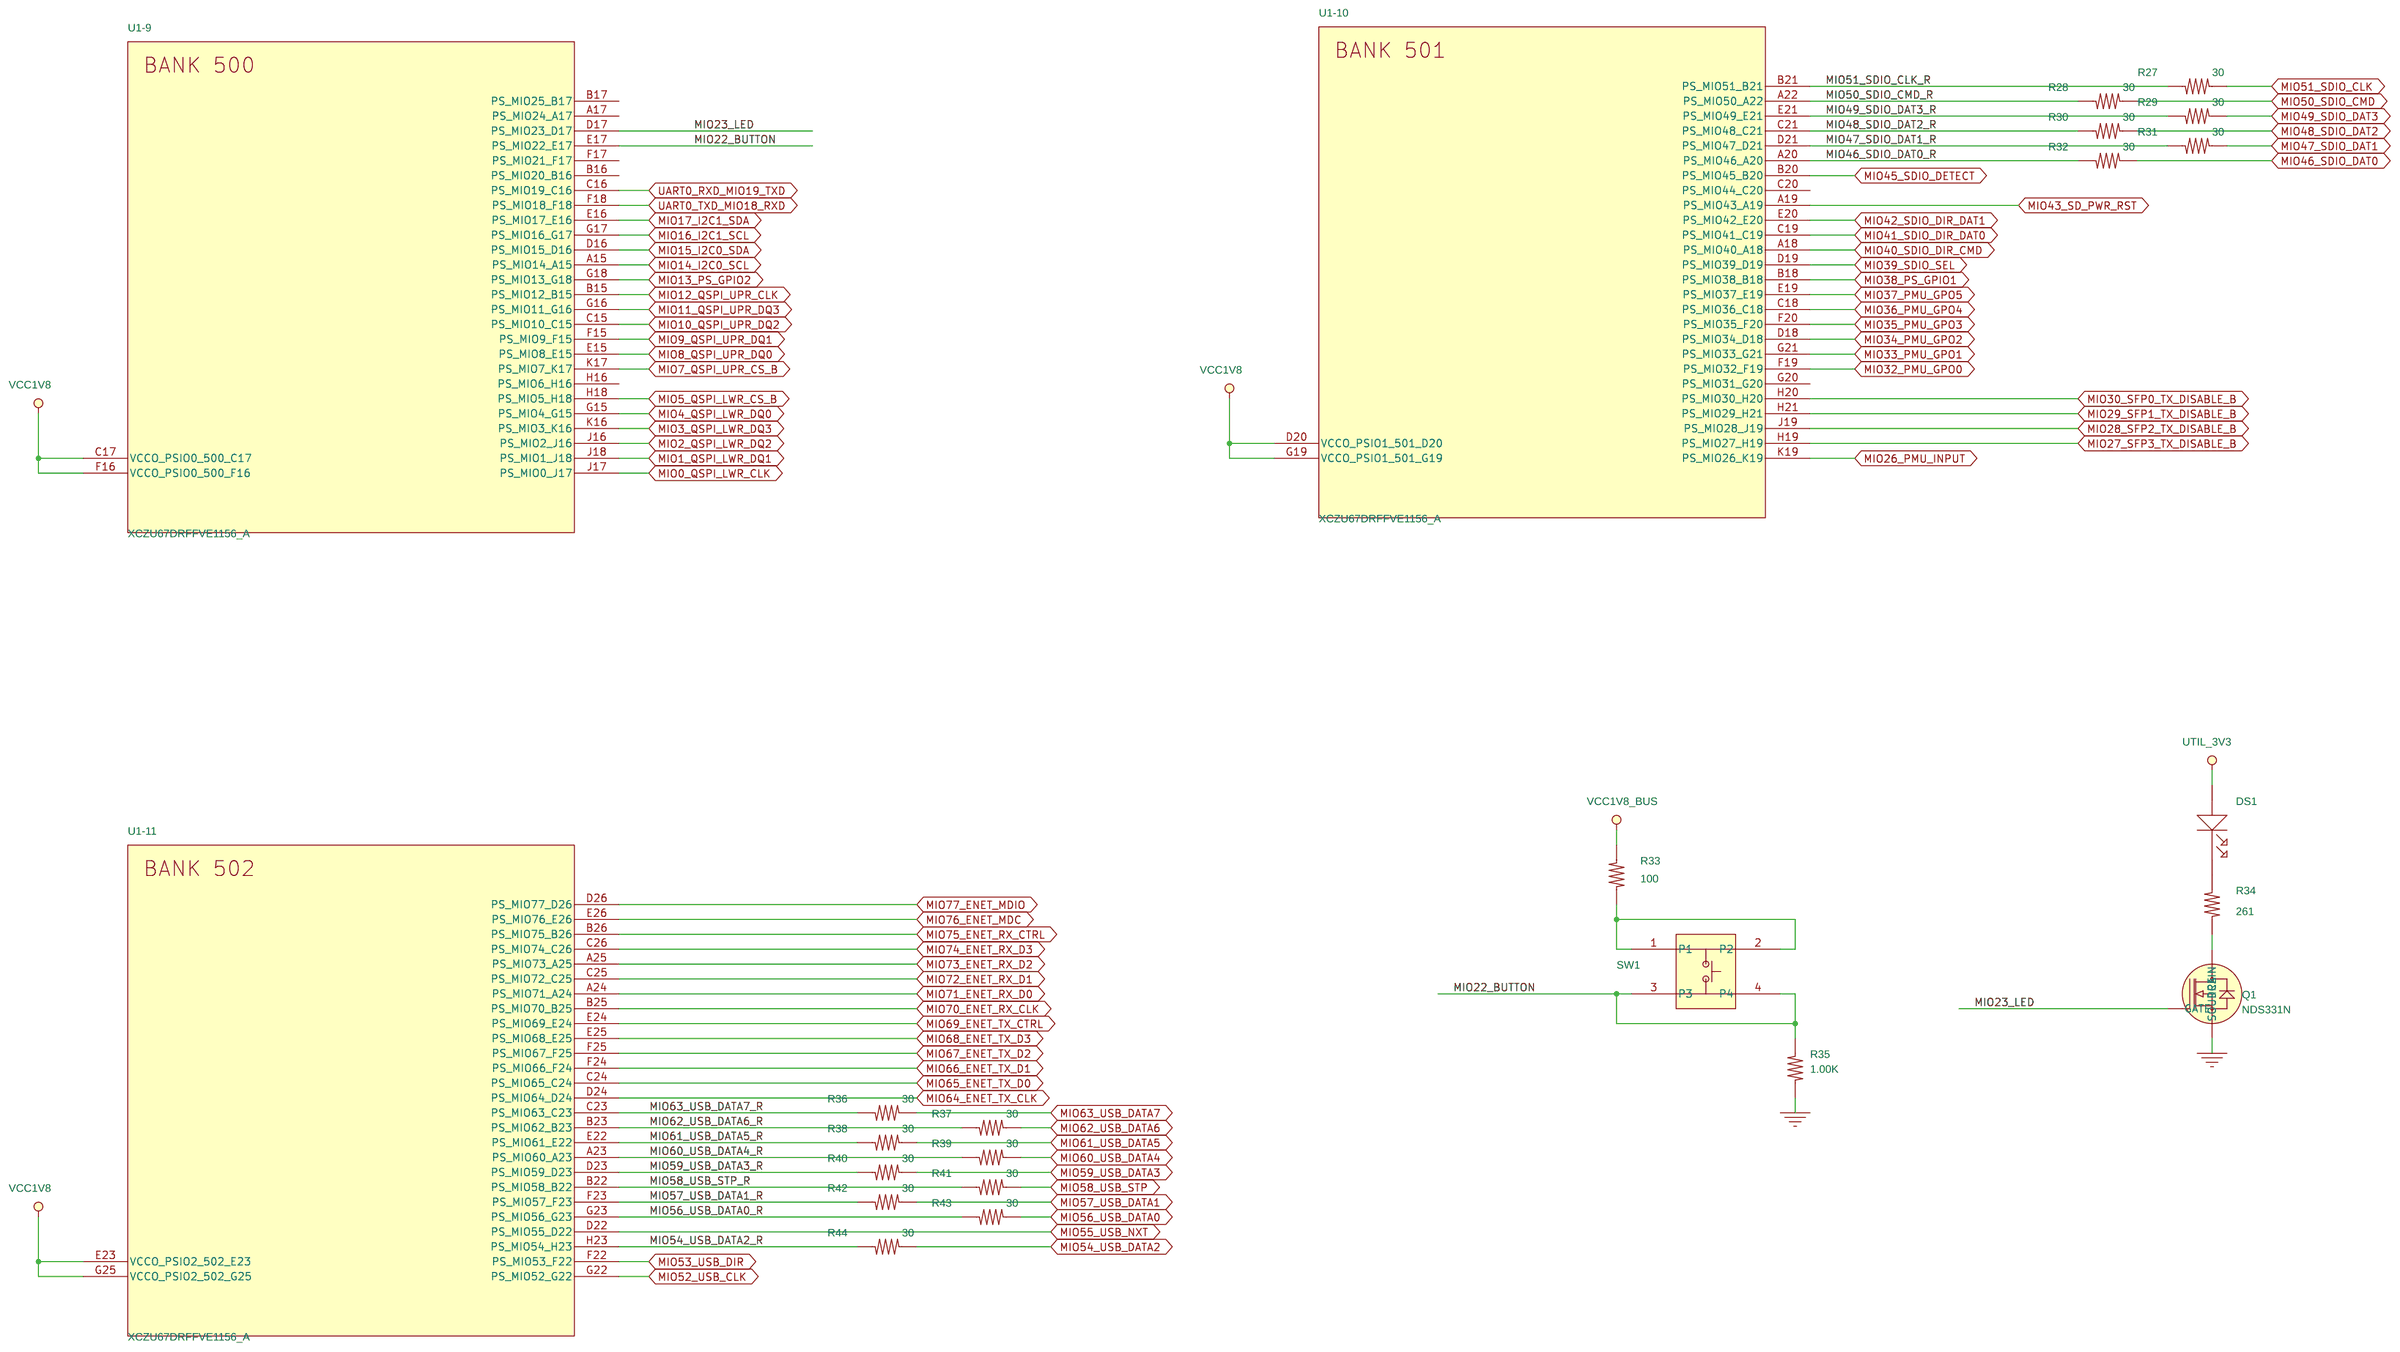
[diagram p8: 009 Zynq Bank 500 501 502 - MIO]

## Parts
sheet 003 Zynq Bank 0
C1  0.1UF  [CAPC100X50X55]
C2  0.47UF  [CAPC100X50X55]
C3  0.1UF  [CAPC100X50X55]
C4  0.47UF  [CAPC100X50X55]
C5  10UF  [CAPC100X50X70]
C6  2700PF  [CAPC100X50X55]
J1  HDR_1X3  [HDR_1X3]
J2  HDR_1X2  [HDR_1X2]
J3  HDR_1X2  [HDR_1X2]
J4  HDR_1X3  [HDR_1X3]
J5  HDR_2X6  [HDR_2X6]
L1  FERRITE-600  [INDC200X125X110]
L2  FERRITE-600  [INDC200X125X110]
R1  1.00K  [RESC100X50X40]
R2  1.00K  [RESC100X50X40]
R3  20.5K  [RESC100X50X40]
R4  20.5K  [RESC100X50X40]
R5  4.70K  [RESC100X50X40]
R6  20.5K  [RESC100X50X40]
R7  100  [RESC100X50X40]
R8  100  [RESC100X50X40]
U2  REF3012AIDBZT  [SOT23_3]
sheet 004 Zynq Bank 65 66
C1586  0.1UF  [CAPC100X50X55]
C1587  0.1UF  [CAPC100X50X55]
C1588  0.1UF  [CAPC100X50X55]
C1589  0.1UF  [CAPC100X50X55]
R11  1.00K  [RESC100X50X40]
R12  1.00K  [RESC100X50X40]
R14  240  [RESC100X50X40]
R17  240  [RESC100X50X40]
R919  100  [RESC100X50X40]
R1033  1.00K  [RESC100X50X40]
R1034  1.00K  [RESC100X50X40]
R1035  1.00K  [RESC100X50X40]
R1036  1.00K  [RESC100X50X40]
R1097  100  [RESC100X50X40]
U410  TXB0108  [TSSOP_20]
U411  TXB0108  [TSSOP_20]
sheet 005 Zynq Bank 67 88
C9  0.1UF  [CAPC100X50X55]
C10  0.1UF  [CAPC100X50X55]
C1518  0.1UF  [CAPC100X50X55]
C1519  0.1UF  [CAPC100X50X55]
J144  32K10K-400L5  [32K10K_400_NEW]
J145  32K10K-400L5  [32K10K_400_NEW]
R9  100  [RESC100X50X40]
R18  240  [RESC100X50X40]
R988  100  [RESC100X50X40]
R1119  100  [RESC100X50X40]
R1749  100  [RESC100X50X40]
R1751  0  [RESC100X50X40]
R1752  0  [RESC100X50X40]
R1753  100  [RESC100X50X40]
sheet 006 Zynq Bank 127 128
C15  0.01UF  [CAPC60X30X33]
C16  0.01UF  [CAPC60X30X33]
C1506  0.01UF  [CAPC60X30X33]
C1507  0.01UF  [CAPC60X30X33]
C1508  0.01UF  [CAPC60X30X33]
C1509  0.01UF  [CAPC60X30X33]
C1510  0.01UF  [CAPC60X30X33]
C1511  0.01UF  [CAPC60X30X33]
R24  100  [RESC100X50X40]
Z80  0201_SHORT  [0201_SHORT]
sheet 007 Zynq Banks ADC
J8  TM14-0084-00  [CONN_CARLISE_TM14_0084_00]
J98  TM14-0084-00  [CONN_CARLISE_TM14_0084_00]
R25  2.49K  [RESC100X50X40]
sheet 008 Zynq Banks DAC
J99  TM14-0084-00  [CONN_CARLISE_TM14_0084_00]
J100  TM14-0084-00  [CONN_CARLISE_TM14_0084_00]
R26  2.49K  [RESC100X50X40]
R1055  0  [RESC100X50X40]
R1056  0  [RESC100X50X40]
sheet 009 Zynq Bank 500 501 502 - MIO
DS1  LED-GRN-SMT  [LED_0603]
Q1  NDS331N  [SOT_23]
R27  30  [RESC100X50X40]
R28  30  [RESC100X50X40]
R29  30  [RESC100X50X40]
R30  30  [RESC100X50X40]
R31  30  [RESC100X50X40]
R32  30  [RESC100X50X40]
R33  100  [RESC100X50X40]
R34  261  [RESC100X50X40]
R35  1.00K  [RESC100X50X40]
R36  30  [RESC100X50X40]
R37  30  [RESC100X50X40]
R38  30  [RESC100X50X40]
R39  30  [RESC100X50X40]
R40  30  [RESC100X50X40]
R41  30  [RESC100X50X40]
R42  30  [RESC100X50X40]
R43  30  [RESC100X50X40]
R44  30  [RESC100X50X40]
SW1  TL3301EF100QG  [SW_TL3301_G_4P]
sheet 016 Zynq Power 2
U1  XCZU67DRFFVE1156_A  [SOC_1156_1MM_IRON_XILINX]  (sections -1,-10,-11,-12,-13,-14,-15,-16,-17,-18,-19,-2,-20,-21,-22,-23,-24,-25,-26,-27,-28,-29,-3,-30,-31,-32,-33,-34,-35,-36,-37,-38,-39,-4,-40,-41,-42,-43,-44,-45,-46,-47,-48,-49,-5,-6,-7,-8,-9)

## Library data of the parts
C1 C3 C1586-C1589 = CAP_NP: Cap Cer 100nF 10% 25V X5R 0402; ALT_SYMBOLS: CAPC100X50X55RND; Agile Part Number: CAP-00068-01; CIP Link: http://xsjbrdwin1/CIP-E/Component/Index/All?pn=100040; Dielectric Type: X5R; OWNER: 4001; PRICE: 0.01; Part Type: CERAMIC; PartType: CERAMIC; ROHS: Yes; Tolerance: 10%; Voltage: 25V; barcode: 100040
C2 C4 = CAP_NP: Cap Cer 470nF 10% 10V X5R 0402; ALT_SYMBOLS: CAPC100X50X55RND; Agile Part Number: CAP-00054-01; CIP Link: http://xsjbrdwin1/CIP-E/Component/Index/All?pn=100022; Dielectric Type: X5R; OWNER: 4001; PRICE: 0.02; Part Type: CERAMIC; PartType: CERAMIC; ROHS: Yes; Tolerance: 10%; Voltage: 10V; barcode: 100022
C5 = CAP_NP: Cap Cer 10uF 20%  6.3V X6S 0402; ALT_SYMBOLS: CAPC100X50X55RND; Agile Part Number: CAP-00035-01; CIP Link: http://xsjbrdwin1/CIP-E/Component/Index/All?pn=100268; Dielectric Type: X6S; OWNER: 3670; PRICE: 0.04; Part Type: CERAMIC; PartType: CERAMIC; ROHS: Yes; Tolerance: 20%; Voltage: 6.3V; barcode: 100268
C6 = CAP_NP: Cap Cer 2.7nF 10% 50V X7R 0402; ALT_SYMBOLS: CAPC100X50X55RND; Agile Part Number: CAP-00133-01; CIP Link: http://xsjbrdwin1/CIP-E/Component/Index/All?pn=100149; Dielectric Type: X7R; OWNER: 3709; PRICE: 0; Part Type: CERAMIC; PartType: CERAMIC; ROHS: Yes; Tolerance: 10%; Voltage: 50V; barcode: 100149
J1 = HDR_1X3: Conn Hdr Vert 3 Pos 1x3 2.54mm P Black TH; Agile Part Number: CON-00038-01; Barcode: 390103; CIP Link: http://xsjbrdwin1/CIP-E/Component/Index/All?pn=390103; Part Type: HEADER; Pitch: 0.100; ROHS: Yes
J2 J3 = HDR_1X2: Conn Hdr Male Vert 2 Pos 1x2 2.54mm P Black TH; Agile Part Number: CON-00037-01; Barcode: 390102; CIP Link: http://xsjbrdwin1/CIP-E/Component/Index/All?pn=390102; OWNER: 4001; PRICE: 0.03; Part Type: HEADER; PartType: HEADER; Pins: 2PINS; Pitch: 0.100; ROHS: Yes
J4 = HDR_1X3: Conn Hdr Vert 3 Pos 1x3 2.54mm P Black TH; Agile Part Number: CON-00038-01; Barcode: 390103; CIP Link: http://xsjbrdwin1/CIP-E/Component/Index/All?pn=390103; Part Type: HEADER; Pins: 3PINS; Pitch: 0.100; ROHS: Yes
J5 = HDR_2X6: Conn Hdr Vert 12 Pos 2x6 2.54mm P Black TH; Agile Part Number: CON-00076-01; Barcode: 390206; CIP Link: http://xsjbrdwin1/CIP-E/Component/Index/All?pn=390206; Part Type: HEADER; Pins: 12PINS; Pitch: 0.100; ROHS: Yes
L1 L2 = IND: Bead 600R 500mA 300mR 0805; Agile Part Number: FLT-00005-01; Barcode: 300009; CIP Link: http://xsjbrdwin1/CIP-E/Component/Index/All?pn=300009; OWNER: 4001; Part Type: FERRITE; PartType: FERRITE; ROHS: Yes
R1 R11 R12 R35 R1033-R1036 = RES: Res 1K 1% 1/16W 100PPM 50V 0402; ALT_SYMBOLS: RESC100X50X40RND; Agile Part Number: RES-00027-01; Barcode: 200098; CIP Link: http://xsjbrdwin1/CIP-E/Component/Index/All?pn=200098; OWNER: 4001; PRICE: 0; Part Type: SMT - 1%; PartType: SMT - 1%; Power: 1/16W; ROHS: Yes; Rated Power: 1/16W; Tolerance: 1%; primarykey: 7
R2 = RES: Res 1K 1% 1/16W 100PPM 50V 0402; ALT_SYMBOLS: RESC100X50X40RND; ASSEMBLY_OPTIONS: DNP; Agile Part Number: RES-00027-01; Barcode: 200098; CIP Link: http://xsjbrdwin1/CIP-E/Component/Index/All?pn=200098; OWNER: 3709; PRICE: 0; Part Type: SMT - 1%; PartType: SMT - DNP; Power: DNP; ROHS: Yes; Rated Power: 1/16W; Tolerance: 1%; primarykey: 73
R3 = RES: Res 20K5 1% 1/16W 100PPM 50V 0402; ALT_SYMBOLS: RESC100X50X40RND; ASSEMBLY_OPTIONS: DNP; Agile Part Number: RES-00080-01; Barcode: 200043; CIP Link: http://xsjbrdwin1/CIP-E/Component/Index/All?pn=200043; OWNER: 3709; PRICE: 0; Part Type: SMT - 1%; PartType: SMT - DNP; Power: DNP; ROHS: Yes; Rated Power: 1/16W; Tolerance: 1%; primarykey: 73
R4 R6 = RES: Res 20K5 1% 1/16W 100PPM 50V 0402; ALT_SYMBOLS: RESC100X50X40RND; Agile Part Number: RES-00080-01; Barcode: 200043; CIP Link: http://xsjbrdwin1/CIP-E/Component/Index/All?pn=200043; OWNER: 10460; PRICE: 0; Part Type: SMT - 1%; PartType: SMT - 1%; Power: 1/10W; ROHS: Yes; Rated Power: 1/16W; Tolerance: 1%; primarykey: 163
R5 = RES: Res 4K7 1% 1/16W 100PPM 50V 0402; ALT_SYMBOLS: RESC100X50X40RND; Agile Part Number: RES-00035-01; Barcode: 200067; CIP Link: http://xsjbrdwin1/CIP-E/Component/Index/All?pn=200067; OWNER: 3670; PRICE: 0.01; Part Type: SMT - 1%; PartType: SMT - 1%; Power: 1/16W; ROHS: Yes; Rated Power: 1/16W; Tolerance: 1%; primarykey: 128
R7-R9 R24 R33 R919 R988 R1097 R1119 R1749 R1753 = RES: Res 100R 1% 1/16W 100PPM 50V 0402; ALT_SYMBOLS: RESC100X50X40RND; Agile Part Number: RES-00046-01; Barcode: 200024; CIP Link: http://xsjbrdwin1/CIP-E/Component/Index/All?pn=200024; OWNER: 4001; PRICE: 0.02; Part Type: SMT - 1%; PartType: SMT - 1%; Power: 1/10W; ROHS: Yes; Rated Power: 1/16W; Tolerance: 1%; primarykey: 12
U2 = REF3012: IC V. Ref 1.25V 0.2% 25mA 24PPM SOT23-3; Agile Part Number: ICS-00474-01; Barcode: 740010; CIP Link: http://xsjbrdwin1/CIP-E/Component/Index/All?pn=740010; Family: REGULATOR; Part Type: REGULATOR; ROHS: Yes
R14 R17 = RES: Res 240R 1% 1/16W 100PPM 50V 0402; ALT_SYMBOLS: RESC100X50X40RND; Agile Part Number: RES-00018-01; Barcode: 200046; CIP Link: http://xsjbrdwin1/CIP-E/Component/Index/All?pn=200046; OWNER: 3670; PRICE: 0; Part Type: SMT - 1%; PartType: SMT - 1%; Power: 1/10W; ROHS: Yes; Rated Power: 1/16W; Tolerance: 1%; primarykey: 103
U410 U411 = TXB0108: IC TRNSLTR BIDIRECTIONAL 20TSSOP; Agile Part Number: ICS-00087-01; Barcode: 500063; CIP Link: http://xsjbrdwin1/CIP-E/Component/Index/All?pn=500063; Part Type: LEVEL TRANSLATOR
C9 C10 C1518 C1519 = CAP_NP: Cap Cer 100nF 10% 25V X5R 0402; ALT_SYMBOLS: CAPC100X50X55RND; Agile Part Number: CAP-00068-01; CIP Link: http://xsjbrdwin1/CIP-E/Component/Index/All?pn=100040; Dielectric Type: X5R; OWNER: 4001; PRICE: 0; Part Type: CERAMIC; PartType: CERAMIC; ROHS: Yes; Tolerance: 10%; Voltage: 25V; barcode: 100040
J144 J145 = SMA-5PIN: Conn Rcpt SMA Vert 50R 12.4GHz SMT/TH; ALT_SYMBOLS: 32K10K_400_3M_73251_DUAL; Agile Part Number: CON-00180-01; Barcode: 400125; CIP Link: http://xsjbrdwin1/CIP-E/Component/Index/All?pn=400125; OWNER: 4001; PRICE: 3.89; Part Type: SMA; PartType: SMA; Pins: 5PINS; ROHS: Yes
R18 = RES: Res 240R 1% 1/16W 100PPM 50V 0402; ALT_SYMBOLS: RESC100X50X40RND; ASSEMBLY_OPTIONS: DNP; Agile Part Number: RES-00018-01; Barcode: 200046; CIP Link: http://xsjbrdwin1/CIP-E/Component/Index/All?pn=200046; OWNER: 3670; PRICE: 0; Part Type: SMT - 1%; PartType: SMT - 1%; Power: 1/10W; ROHS: Yes; Rated Power: 1/16W; Tolerance: 1%; primarykey: 103
R1055 R1056 R1751 R1752 = RES: Res 0R 50mR 1A 0402; ALT_SYMBOLS: RESC100X50X40RND; Agile Part Number: RES-00010-01; Barcode: 200012; CIP Link: http://xsjbrdwin1/CIP-E/Component/Index/All?pn=200012; Part Type: SMT - 5%; Tolerance: 5%
C15 C16 C1506-C1511 = CAP_NP: Cap Cer 10nF 10% 16V X5R 0201; Agile Part Number: CAP-00144-01; Barcode: 100164; CIP Link: http://xsjbrdwin1/CIP-E/Component/Index/All?pn=100164; Dielectric Type: X5R; Part Type: CERAMIC; Tolerance: 10%; Voltage: 16V
Z80 = 0201_SHORT: PCB only 0201_SHORT; ASSEMBLY_OPTIONS: DNP; Barcode: 96000001; CIP Link: http://xsjbrdwin1/CIP-E/Component/Index/All?pn=96000001; OWNER: 3670; Part Type: PCB LAYOUT; PartType: PCB LAYOUT; ROHS: 0
J8 J98-J100 = SMA-5PIN: Conn Rcpt SSMP Male Vert 50R 50GHz SMT/TH Non-Detent; Agile Part Number: CON-00301-01; Barcode: 40000016; CIP Link: http://xsjbrdwin1/CIP-E/Component/Index/All?pn=40000016; Number of Pins: 5; Part Type: --\--
R25 R26 = RES: Res 2K49 1% 1/16W 100PPM 50V 0402; Agile Part Number: RES-00085-01; Barcode: 200049; CIP Link: http://xsjbrdwin1/CIP-E/Component/Index/All?pn=200049; OWNER: 10460; PRICE: 0; Part Type: SMT - 1%; PartType: SMT - 1%; Power: 1/10W; ROHS: Yes; Rated Power: 1/16W; Tolerance: 1%; primarykey: 161
DS1 = LED: LED Green Diffused 20mA 5V 570nm 0603; Agile Part Number: DIO-00003-01; Barcode: 300021; CIP Link: http://xsjbrdwin1/CIP-E/Component/Index/All?pn=300021; OWNER: 4001; PRICE: 0.1; Power: 2.2-20MA; ROHS: Yes; Rated Power: 2.2-20MA; Voltage: 2.2V
Q1 = FET-3PIN: MOSFET N-Ch 20V 1.3A 160mR SSOT-3; Agile Part Number: TRN-00012-01; Barcode: 500100; CIP Link: http://xsjbrdwin1/CIP-E/Component/Index/All?pn=500100; OWNER: 4001; PRICE: 0.12; Part Type: FET; PartType: FET; Power: 460MW; ROHS: Yes; Rated Power: 460MW; Rated Voltage: 20V
R27-R32 R36-R44 = RES: Res 30R 1% 1/16W 100PPM 50V 0402; Agile Part Number: RES-00143-01; Barcode: 200133; CIP Link: http://xsjbrdwin1/CIP-E/Component/Index/All?pn=200133; OWNER: 3709; PRICE: 0; Part Type: SMT - 1%; PartType: SMT - 1%; Power: 1/10W; ROHS: Yes; Rated Power: 1/16W; Tolerance: 1%; primarykey: 93
R34 = RES: Res 261R 1% 1/16W 100PPM 50V 0402; ALT_SYMBOLS: RESC100X50X40RND; Agile Part Number: RES-00086-01; Barcode: 200050; CIP Link: http://xsjbrdwin1/CIP-E/Component/Index/All?pn=200050; OWNER: 3501; PRICE: 0; Part Type: SMT - 1%; PartType: SMT - 1%; Power: 1/10W; ROHS: Yes; Rated Power: 1/16W; Tolerance: 1%; primarykey: 60
SW1 = PUSHBUTTON-4: Switch SPST-NO Mom 50mA 50V 7.3mm H 100gf SMT; Agile Part Number: SWH-00014-01; Barcode: 440011; CIP Link: http://xsjbrdwin1/CIP-E/Component/Index/All?pn=440011; OWNER: 3709; PRICE: 0.25; Part Type: MOMENT; PartType: MOMENT; ROHS: Yes
U1 = XCZU67DRFFVE1156_A

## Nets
GND: C1586.2 C1587.2 C1588.2 C1589.2 J1.3(P3) J8.2(GND1) J8.3(GND2) J8.4(GND3) J8.5(GND4) J98.2(GND1) J98.3(GND2) J98.4(GND3) J98.5(GND4) J99.2(GND1) J99.3(GND2) J99.4(GND3) J99.5(GND4) J100.2(GND1) J100.3(GND2) J100.4(GND3) J100.5(GND4) J144.2(GND1) J144.3(GND2) J144.4(GND3) J144.5(GND4) J145.2(GND1) J145.3(GND2) J145.4(GND3) J145.5(GND4) L2.2 Q1.2(SOURCE) R2.2 R4.2 R5.2 R6.2 R11.2 R12.2 R14.2 R17.2 R18.2 R25.2 R26.2 R35.2 R1035.2 R1036.2 U410.11(GND) U411.11(GND) ; also on sheet 10 11 12 13 14 16 17 18 19 20 21 22 23 24 25 26 27 28 32 33 34 35 36 37 38 39 40 41 42 43 44 45 46 47 48 49 50 51 52 53 54 55 56 57 58 59 60 61 62 63 64 65 66 67 68 69 70 71 72
VCC1V2: C1587.1 C1589.1 R1033.1 R1034.1 U1.AE12(VCCO_66) U1.AF15(VCCO_65) U1.AH11(VCCO_66) U1.AJ14(VCCO_65) U1.AK17(VCCO_65) U1.AL10(VCCO_66) U410.2(VCCA) U410.10(OE) U411.2(VCCA) U411.10(OE) ; also on sheet 11 17 25 27 40 41 42 48 59 65 66 67 68
VCC1V8: L1.2 R1.1 R3.1 U1.C17(VCCO_PSIO0_500) U1.D10(VCCO_88) U1.D20(VCCO_PSIO1_501) U1.E13(VCCO_67) U1.E23(VCCO_PSIO2_502) U1.F16(VCCO_PSIO0_500) U1.G9(VCCO_88) U1.G19(VCCO_PSIO1_501) U1.G25(VCCO_PSIO2_502) U1.H12(VCCO_67) ; also on sheet 10 15 16 17 52 69
VCC1V8_BUS: C1586.1 C1588.1 R33.1 U410.19(VCCB) U411.19(VCCB) ; also on sheet 10 12 20 21 22 23 24 25 26 27 34 36 37 38 39 42 52 61 62 64
VCCINT: J1.1(P1) ; also on sheet 15 17 44 45 69
VCCINT_VIN_R_N: J5.11(P11) ; also on sheet 45
VCCINT_VIN_R_P: J5.12(P12) ; also on sheet 45
8A34001_CLK1_IN_C_N: C1511.1 U1.M29(MGTREFCLK0N_127)
8A34001_CLK1_IN_C_P: C1510.1 U1.M28(MGTREFCLK0P_127)
8A34001_CLK1_IN_N: C1511.2 ; also on sheet 38
8A34001_CLK1_IN_P: C1510.2 ; also on sheet 38
8A34001_CLK2_IN_C_N: C1507.1 U1.H29(MGTREFCLK0N_128)
8A34001_CLK2_IN_C_P: C1506.1 U1.H28(MGTREFCLK0P_128)
8A34001_CLK2_IN_N: C1507.2 ; also on sheet 38
8A34001_CLK2_IN_P: C1506.2 ; also on sheet 38
8A34001_CLK6_IN_C_N: C10.1 U1.D11(IO_L5N_HDGC_AD7N_88)
8A34001_CLK6_IN_C_P: C9.1 U1.E11(IO_L5P_HDGC_AD7P_88)
8A34001_CLK6_IN_N: C10.2 ; also on sheet 38
8A34001_CLK6_IN_P: C9.2 ; also on sheet 38
8A34001_Q2_OUT_N: R1119.2 U1.F9(IO_L7N_HDGC_AD5N_88) ; also on sheet 38
8A34001_Q2_OUT_P: R1119.1 U1.F10(IO_L7P_HDGC_AD5P_88) ; also on sheet 38
8A34001_Q3_OUT_N: R988.2 U1.D12(IO_L12N_T1U_N11_GC_67) ; also on sheet 38
8A34001_Q3_OUT_P: R988.1 U1.E12(IO_L12P_T1U_N10_GC_67) ; also on sheet 38
8A34001_Q11_OUT_C_N: C1509.1 U1.F29(MGTREFCLK1N_128)
8A34001_Q11_OUT_C_P: C1508.1 U1.F28(MGTREFCLK1P_128)
8A34001_Q11_OUT_N: C1509.2 ; also on sheet 38
8A34001_Q11_OUT_P: C1508.2 ; also on sheet 38
ADC224_T0_CH0_N: U1.AK1(ADC_VIN0_N_224) ; also on sheet 61
ADC224_T0_CH0_P: U1.AK2(ADC_VIN0_P_224) ; also on sheet 61
ADC224_T0_CH1_N: U1.AH1(ADC_VIN1_N_224) ; also on sheet 61
ADC224_T0_CH1_P: U1.AH2(ADC_VIN1_P_224) ; also on sheet 61
ADC224_T0_CH2_N: U1.AF1(ADC_VIN2_N_224) ; also on sheet 61
ADC224_T0_CH2_P: U1.AF2(ADC_VIN2_P_224) ; also on sheet 61
ADC224_T0_CH3_N: U1.AD1(ADC_VIN3_N_224) ; also on sheet 61
ADC224_T0_CH3_P: U1.AD2(ADC_VIN3_P_224) ; also on sheet 61
ADC225_T1_CH0_N: U1.AB1(ADC_VIN0_N_225) ; also on sheet 61
ADC225_T1_CH0_P: U1.AB2(ADC_VIN0_P_225) ; also on sheet 61
ADC225_T1_CH1_N: U1.Y1(ADC_VIN1_N_225) ; also on sheet 61
ADC225_T1_CH1_P: U1.Y2(ADC_VIN1_P_225) ; also on sheet 61
ADC225_T1_CH2_N: U1.V1(ADC_VIN2_N_225) ; also on sheet 61
ADC225_T1_CH2_P: U1.V2(ADC_VIN2_P_225) ; also on sheet 61
ADC225_T1_CH3_N: U1.T1(ADC_VIN3_N_225) ; also on sheet 61
ADC225_T1_CH3_P: U1.T2(ADC_VIN3_P_225) ; also on sheet 61
ADC226_T2_CH01_N: U1.Y5(ADC_VIN_I01_N_226) ; also on sheet 61
ADC226_T2_CH01_P: U1.Y4(ADC_VIN_I01_P_226) ; also on sheet 61
ADC226_T2_CH23_N: U1.V5(ADC_VIN_I23_N_226) ; also on sheet 61
ADC226_T2_CH23_P: U1.V4(ADC_VIN_I23_P_226) ; also on sheet 61
ADC_CLK_226_N: J98.1(SIG) U1.AB4(ADC_CLK_N_226)
ADC_CLK_226_P: J8.1(SIG) U1.AB5(ADC_CLK_P_226)
ADCIO_00: U1.A13(IO_L9N_T1L_N5_AD12N_67) ; also on sheet 61
ADCIO_01: U1.A14(IO_L9P_T1L_N4_AD12P_67) ; also on sheet 61
ADCIO_02: U1.B13(IO_L8N_T1L_N3_AD5N_67) ; also on sheet 61
ADCIO_03: U1.C14(IO_L8P_T1L_N2_AD5P_67) ; also on sheet 61
ADCIO_04: U1.C13(IO_L7N_T1L_N1_QBC_AD13N_67) ; also on sheet 61
ADCIO_05: U1.D13(IO_L7P_T1L_N0_QBC_AD13P_67) ; also on sheet 61
ADCIO_06: U1.F13(IO_L5N_T0U_N9_AD14N_67) ; also on sheet 61
ADCIO_07: U1.F14(IO_L5P_T0U_N8_AD14P_67) ; also on sheet 61
ADCIO_08: U410.20(B1) ; also on sheet 61
ADCIO_08_LS: U1.AN9(IO_T1U_N12_66) U410.1(A1)
ADCIO_09: U410.18(B2) ; also on sheet 61
ADCIO_09_LS: U1.AN7(IO_L9N_T1L_N5_AD12N_66) U410.3(A2)
ADCIO_10: U410.17(B3) ; also on sheet 61
ADCIO_10_LS: U1.AN8(IO_L9P_T1L_N4_AD12P_66) U410.4(A3)
ADCIO_11: U410.16(B4) ; also on sheet 61
ADCIO_11_LS: U1.AP12(IO_L7N_T1L_N1_QBC_AD13N_66) U410.5(A4)
ADCIO_12: U410.15(B5) ; also on sheet 61
ADCIO_12_LS: U1.AP13(IO_L7P_T1L_N0_QBC_AD13P_66) U410.6(A5)
ADCIO_13: U410.14(B6) ; also on sheet 61
ADCIO_13_LS: U1.AN1(IO_L6N_T0U_N11_AD6N_66) U410.7(A6)
ADCIO_14: U410.13(B7) ; also on sheet 61
ADCIO_14_LS: U1.AN2(IO_L6P_T0U_N10_AD6P_66) U410.8(A7)
ADCIO_15: U410.12(B8) ; also on sheet 61
ADCIO_15_LS: U1.AP2(IO_L5N_T0U_N9_AD14N_66) U410.9(A8)
CLK104_CLK_SPI_MUX_SEL0_LS: U1.F12(IO_L6N_T0U_N11_AD6N_67) ; also on sheet 64
CLK104_CLK_SPI_MUX_SEL1_LS: U1.G12(IO_L6P_T0U_N10_AD6P_67) ; also on sheet 64
CLK104_PL_CLK_N: R1753.2 U1.G10(IO_L8N_HDGC_AD4N_88) ; also on sheet 64
CLK104_PL_CLK_P: R1753.1 U1.G11(IO_L8P_HDGC_AD4P_88) ; also on sheet 64
CPU_RESET: U1.H11(IO_L11N_AD1N_88) ; also on sheet 37
DAC227_T0_CH0_N: U1.N1(DAC_VOUT0_N_227) ; also on sheet 62
DAC227_T0_CH0_P: U1.N2(DAC_VOUT0_P_227) ; also on sheet 62
DAC227_T0_CH1_N: U1.L1(DAC_VOUT1_N_227) ; also on sheet 62
DAC227_T0_CH1_P: U1.L2(DAC_VOUT1_P_227) ; also on sheet 62
DAC227_T0_CH2_N: U1.J1(DAC_VOUT2_N_227) ; also on sheet 62
DAC227_T0_CH2_P: U1.J2(DAC_VOUT2_P_227) ; also on sheet 62
DAC227_T0_CH3_N: U1.G1(DAC_VOUT3_N_227) ; also on sheet 62
DAC227_T0_CH3_P: U1.G2(DAC_VOUT3_P_227) ; also on sheet 62
DAC228_T1_CH0_N: U1.E1(DAC_VOUT0_N_228) ; also on sheet 62
DAC228_T1_CH0_P: U1.E2(DAC_VOUT0_P_228) ; also on sheet 62
DAC228_T1_CH1_N: U1.C1(DAC_VOUT1_N_228) ; also on sheet 62
DAC228_T1_CH1_P: U1.C2(DAC_VOUT1_P_228) ; also on sheet 62
DAC228_T1_CH2_N: U1.A4(DAC_VOUT2_N_228) ; also on sheet 62
DAC228_T1_CH2_P: U1.B4(DAC_VOUT2_P_228) ; also on sheet 62
DAC228_T1_CH3_N: U1.A6(DAC_VOUT3_N_228) ; also on sheet 62
DAC228_T1_CH3_P: U1.B6(DAC_VOUT3_P_228) ; also on sheet 62
DAC_CLK_228_N: J100.1(SIG) U1.J4(DAC_CLK_N_228)
DAC_CLK_228_P: J99.1(SIG) U1.J5(DAC_CLK_P_228)
DACIO_00: U1.G13(IO_L4N_T0U_N7_DBC_AD7N_67) ; also on sheet 62
DACIO_01: U1.H13(IO_L4P_T0U_N6_DBC_AD7P_67) ; also on sheet 62
DACIO_02: U1.J13(IO_L3N_T0L_N5_AD15N_67) ; also on sheet 62
DACIO_03: U1.J14(IO_L3P_T0L_N4_AD15P_67) ; also on sheet 62
DACIO_04: U1.H14(IO_L2N_T0L_N3_67) ; also on sheet 62
DACIO_05: U1.H15(IO_L2P_T0L_N2_67) ; also on sheet 62
DACIO_06: U1.K14(IO_L1N_T0L_N1_DBC_67) ; also on sheet 62
DACIO_07: U1.K15(IO_L1P_T0L_N0_DBC_67) ; also on sheet 62
DACIO_08: U411.20(B1) ; also on sheet 62
DACIO_08_LS: U1.AP3(IO_L5P_T0U_N8_AD14P_66) U411.1(A1)
DACIO_09: U411.18(B2) ; also on sheet 62
DACIO_09_LS: U1.AN4(IO_L4N_T0U_N7_DBC_AD7N_66) U411.3(A2)
DACIO_10: U411.17(B3) ; also on sheet 62
DACIO_10_LS: U1.AN5(IO_L4P_T0U_N6_DBC_AD7P_66) U411.4(A3)
DACIO_11: U411.16(B4) ; also on sheet 62
DACIO_11_LS: U1.AM5(IO_L3N_T0L_N5_AD15N_66) U411.5(A4)
DACIO_12: U411.15(B5) ; also on sheet 62
DACIO_12_LS: U1.AP5(IO_L2N_T0L_N3_66) U411.6(A5)
DACIO_13: U411.14(B6) ; also on sheet 62
DACIO_13_LS: U1.AP6(IO_L2P_T0L_N2_66) U411.7(A6)
DACIO_14: U411.13(B7) ; also on sheet 62
DACIO_14_LS: U1.AP7(IO_L1N_T0L_N1_DBC_66) U411.8(A7)
DACIO_15: U411.12(B8) ; also on sheet 62
DACIO_15_LS: U1.AP8(IO_L1P_T0L_N0_DBC_66) U411.9(A8)
FMCP_HSPC_DP0_C2M_N: U1.E31(MGTYTXN0_128) ; also on sheet 28
FMCP_HSPC_DP0_C2M_P: U1.E30(MGTYTXP0_128) ; also on sheet 28
FMCP_HSPC_DP0_M2C_N: U1.F34(MGTYRXN0_128) ; also on sheet 28
FMCP_HSPC_DP0_M2C_P: U1.F33(MGTYRXP0_128) ; also on sheet 28
FMCP_HSPC_DP1_C2M_N: U1.D29(MGTYTXN1_128) ; also on sheet 28
FMCP_HSPC_DP1_C2M_P: U1.D28(MGTYTXP1_128) ; also on sheet 28
FMCP_HSPC_DP1_M2C_N: U1.D34(MGTYRXN1_128) ; also on sheet 28
FMCP_HSPC_DP1_M2C_P: U1.D33(MGTYRXP1_128) ; also on sheet 28
FMCP_HSPC_DP2_C2M_N: U1.C31(MGTYTXN2_128) ; also on sheet 28
FMCP_HSPC_DP2_C2M_P: U1.C30(MGTYTXP2_128) ; also on sheet 28
FMCP_HSPC_DP2_M2C_N: U1.B34(MGTYRXN2_128) ; also on sheet 28
FMCP_HSPC_DP2_M2C_P: U1.B33(MGTYRXP2_128) ; also on sheet 28
FMCP_HSPC_DP3_C2M_N: U1.B29(MGTYTXN3_128) ; also on sheet 28
FMCP_HSPC_DP3_C2M_P: U1.B28(MGTYTXP3_128) ; also on sheet 28
FMCP_HSPC_DP3_M2C_N: U1.A32(MGTYRXN3_128) ; also on sheet 28
FMCP_HSPC_DP3_M2C_P: U1.A31(MGTYRXP3_128) ; also on sheet 28
FPGA_SYSMON_AVCC: C1.1 C2.1 C4.1 J5.8(P8) L1.1 U1.R14(VCCADC) U2.1(IN)
GPIO_LED0_LS: U1.C9(IO_L4N_AD8N_88) ; also on sheet 37
GPIO_LED1_LS: U1.D9(IO_L4P_AD8P_88) ; also on sheet 37
GPIO_LED2_LS: U1.A9(IO_L3N_AD9N_88) ; also on sheet 37
GPIO_LED3_LS: U1.A10(IO_L3P_AD9P_88) ; also on sheet 37
GPIO_SW_PL: U1.J11(IO_L11P_AD1P_88) ; also on sheet 37
MGT1V2: Z80.2(NET2) ; also on sheet 15 16 17 18 49 69
MGTAVTTRCAL: R24.2 U1.G29(MGTAVTTRCAL_L) Z80.1(NET1)
MGTRREF: R24.1 U1.G28(MGTRREF_L)
MIO0_QSPI_LWR_CLK: U1.J17(PS_MIO0) ; also on sheet 21
MIO1_QSPI_LWR_DQ1: U1.J18(PS_MIO1) ; also on sheet 21
MIO2_QSPI_LWR_DQ2: U1.J16(PS_MIO2) ; also on sheet 21
MIO3_QSPI_LWR_DQ3: U1.K16(PS_MIO3) ; also on sheet 21
MIO4_QSPI_LWR_DQ0: U1.G15(PS_MIO4) ; also on sheet 21
MIO5_QSPI_LWR_CS_B: U1.H18(PS_MIO5) ; also on sheet 21
MIO7_QSPI_UPR_CS_B: U1.K17(PS_MIO7) ; also on sheet 21
MIO8_QSPI_UPR_DQ0: U1.E15(PS_MIO8) ; also on sheet 21
MIO9_QSPI_UPR_DQ1: U1.F15(PS_MIO9) ; also on sheet 21
MIO10_QSPI_UPR_DQ2: U1.C15(PS_MIO10) ; also on sheet 21
MIO11_QSPI_UPR_DQ3: U1.G16(PS_MIO11) ; also on sheet 21
MIO12_QSPI_UPR_CLK: U1.B15(PS_MIO12) ; also on sheet 21
MIO13_PS_GPIO2: U1.G18(PS_MIO13) ; also on sheet 27
MIO14_I2C0_SCL: U1.A15(PS_MIO14) ; also on sheet 22
MIO15_I2C0_SDA: U1.D16(PS_MIO15) ; also on sheet 22
MIO16_I2C1_SCL: U1.G17(PS_MIO16) ; also on sheet 23
MIO17_I2C1_SDA: U1.E16(PS_MIO17) ; also on sheet 23
MIO22_BUTTON: R35.1 SW1.3(P3) SW1.4(P4) U1.E17(PS_MIO22)
MIO23_LED: Q1.1(GATE) U1.D17(PS_MIO23)
MIO26_PMU_INPUT: U1.K19(PS_MIO26) ; also on sheet 25
MIO27_SFP3_TX_DISABLE_B: U1.H19(PS_MIO27) ; also on sheet 33
MIO28_SFP2_TX_DISABLE_B: U1.J19(PS_MIO28) ; also on sheet 33
MIO29_SFP1_TX_DISABLE_B: U1.H21(PS_MIO29) ; also on sheet 33
MIO30_SFP0_TX_DISABLE_B: U1.H20(PS_MIO30) ; also on sheet 33
MIO32_PMU_GPO0: U1.F19(PS_MIO32) ; also on sheet 27
MIO33_PMU_GPO1: U1.G21(PS_MIO33) ; also on sheet 27
MIO34_PMU_GPO2: U1.D18(PS_MIO34) ; also on sheet 27
MIO35_PMU_GPO3: U1.F20(PS_MIO35) ; also on sheet 27
MIO36_PMU_GPO4: U1.C18(PS_MIO36) ; also on sheet 27
MIO37_PMU_GPO5: U1.E19(PS_MIO37) ; also on sheet 27
MIO38_PS_GPIO1: U1.B18(PS_MIO38) ; also on sheet 27
MIO39_SDIO_SEL: U1.D19(PS_MIO39) ; also on sheet 24
MIO40_SDIO_DIR_CMD: U1.A18(PS_MIO40) ; also on sheet 24
MIO41_SDIO_DIR_DAT0: U1.C19(PS_MIO41) ; also on sheet 24
MIO42_SDIO_DIR_DAT1: U1.E20(PS_MIO42) ; also on sheet 24
MIO43_SD_PWR_RST: U1.A19(PS_MIO43) ; also on sheet 24
MIO45_SDIO_DETECT: U1.B20(PS_MIO45) ; also on sheet 24
MIO46_SDIO_DAT0: R32.2 ; also on sheet 24
MIO46_SDIO_DAT0_R: R32.1 U1.A20(PS_MIO46)
MIO47_SDIO_DAT1: R31.2 ; also on sheet 24
MIO47_SDIO_DAT1_R: R31.1 U1.D21(PS_MIO47)
MIO48_SDIO_DAT2: R30.2 ; also on sheet 24
MIO48_SDIO_DAT2_R: R30.1 U1.C21(PS_MIO48)
MIO49_SDIO_DAT3: R29.2 ; also on sheet 24
MIO49_SDIO_DAT3_R: R29.1 U1.E21(PS_MIO49)
MIO50_SDIO_CMD: R28.2 ; also on sheet 24
MIO50_SDIO_CMD_R: R28.1 U1.A22(PS_MIO50)
MIO51_SDIO_CLK: R27.2 ; also on sheet 24
MIO51_SDIO_CLK_R: R27.1 U1.B21(PS_MIO51)
MIO52_USB_CLK: U1.G22(PS_MIO52) ; also on sheet 20
MIO53_USB_DIR: U1.F22(PS_MIO53) ; also on sheet 20
MIO54_USB_DATA2: R44.2 ; also on sheet 20
MIO54_USB_DATA2_R: R44.1 U1.H23(PS_MIO54)
MIO55_USB_NXT: U1.D22(PS_MIO55) ; also on sheet 20
MIO56_USB_DATA0: R43.2 ; also on sheet 20
MIO56_USB_DATA0_R: R43.1 U1.G23(PS_MIO56)
MIO57_USB_DATA1: R42.2 ; also on sheet 20
MIO57_USB_DATA1_R: R42.1 U1.F23(PS_MIO57)
MIO58_USB_STP: R41.2 ; also on sheet 20
MIO58_USB_STP_R: R41.1 U1.B22(PS_MIO58)
MIO59_USB_DATA3: R40.2 ; also on sheet 20
MIO59_USB_DATA3_R: R40.1 U1.D23(PS_MIO59)
MIO60_USB_DATA4: R39.2 ; also on sheet 20
MIO60_USB_DATA4_R: R39.1 U1.A23(PS_MIO60)
MIO61_USB_DATA5: R38.2 ; also on sheet 20
MIO61_USB_DATA5_R: R38.1 U1.E22(PS_MIO61)
MIO62_USB_DATA6: R37.2 ; also on sheet 20
MIO62_USB_DATA6_R: R37.1 U1.B23(PS_MIO62)
MIO63_USB_DATA7: R36.2 ; also on sheet 20
MIO63_USB_DATA7_R: R36.1 U1.C23(PS_MIO63)
MIO64_ENET_TX_CLK: U1.D24(PS_MIO64) ; also on sheet 26
MIO65_ENET_TX_D0: U1.C24(PS_MIO65) ; also on sheet 26
MIO66_ENET_TX_D1: U1.F24(PS_MIO66) ; also on sheet 26
MIO67_ENET_TX_D2: U1.F25(PS_MIO67) ; also on sheet 26
MIO68_ENET_TX_D3: U1.E25(PS_MIO68) ; also on sheet 26
MIO69_ENET_TX_CTRL: U1.E24(PS_MIO69) ; also on sheet 26
MIO70_ENET_RX_CLK: U1.B25(PS_MIO70) ; also on sheet 26
MIO71_ENET_RX_D0: U1.A24(PS_MIO71) ; also on sheet 26
MIO72_ENET_RX_D1: U1.C25(PS_MIO72) ; also on sheet 26
MIO73_ENET_RX_D2: U1.A25(PS_MIO73) ; also on sheet 26
MIO74_ENET_RX_D3: U1.C26(PS_MIO74) ; also on sheet 26
MIO75_ENET_RX_CTRL: U1.B26(PS_MIO75) ; also on sheet 26
MIO76_ENET_MDC: U1.E26(PS_MIO76) ; also on sheet 26
MIO77_ENET_MDIO: U1.D26(PS_MIO77) ; also on sheet 26
MSP430_GPIO_PL_0_LS: U1.B10(IO_L2N_AD10N_88) ; also on sheet 27
MSP430_GPIO_PL_1_LS: U1.C10(IO_L2P_AD10P_88) ; also on sheet 27
MSP430_GPIO_PL_2_LS: U1.B11(IO_L1N_AD11N_88) ; also on sheet 27
MSP430_GPIO_PL_3_LS: U1.C11(IO_L1P_AD11P_88) ; also on sheet 27
MSP430_UCA1_RXD_LS: U1.AJ13(IO_L7N_T1L_N1_QBC_AD13N_65) ; also on sheet 27
MSP430_UCA1_TXD_LS: U1.AL16(IO_T1U_N12_65) ; also on sheet 27
MUX_AMS_SYSREF_C_N: R1055.1 U1.N4(SYSREF_N_227)
MUX_AMS_SYSREF_C_P: R1056.1 U1.N5(SYSREF_P_227)
MUX_AMS_SYSREF_N: R1055.2 ; also on sheet 39
MUX_AMS_SYSREF_P: R1056.2 ; also on sheet 39
MUX_PL_SYSREF_N: R1749.2 U1.E9(IO_L6N_HDGC_AD6N_88) ; also on sheet 39
MUX_PL_SYSREF_P: R1749.1 U1.E10(IO_L6P_HDGC_AD6P_88) ; also on sheet 39
PL_DDR4_C0_A0: U1.AG12(IO_L19P_T3L_N0_DBC_AD9P_66) ; also on sheet 65 66 67 68
PL_DDR4_C0_A1: U1.AJ12(IO_T2U_N12_66) ; also on sheet 65 66 67 68
PL_DDR4_C0_A2: U1.AK11(IO_L18N_T2U_N11_AD2N_66) ; also on sheet 65 66 67 68
PL_DDR4_C0_A3: U1.AJ11(IO_L18P_T2U_N10_AD2P_66) ; also on sheet 65 66 67 68
PL_DDR4_C0_A4: U1.AK9(IO_L17N_T2U_N9_AD10N_66) ; also on sheet 65 66 67 68
PL_DDR4_C0_A5: U1.AK10(IO_L17P_T2U_N8_AD10P_66) ; also on sheet 65 66 67 68
PL_DDR4_C0_A6: U1.AL11(IO_L16N_T2U_N7_QBC_AD3N_66) ; also on sheet 65 66 67 68
PL_DDR4_C0_A7: U1.AL12(IO_L16P_T2U_N6_QBC_AD3P_66) ; also on sheet 65 66 67 68
PL_DDR4_C0_A8: U1.AL13(IO_L15N_T2L_N5_AD11N_66) ; also on sheet 65 66 67 68
PL_DDR4_C0_A9: U1.AK13(IO_L15P_T2L_N4_AD11P_66) ; also on sheet 65 66 67 68
PL_DDR4_C0_A10: U1.AM11(IO_L14N_T2L_N3_GC_66) ; also on sheet 65 66 67 68
PL_DDR4_C0_A11: U1.AM12(IO_L14P_T2L_N2_GC_66) ; also on sheet 65 66 67 68
PL_DDR4_C0_A12: U1.AN12(IO_L8N_T1L_N3_AD5N_66) ; also on sheet 65 66 67 68
PL_DDR4_C0_A13: U1.AN13(IO_L8P_T1L_N2_AD5P_66) ; also on sheet 65 66 67 68
PL_DDR4_C0_ACT_B: U1.AH9(IO_L20N_T3L_N3_AD1N_66) ; also on sheet 65 66 67 68
PL_DDR4_C0_ALERT_B: U1.AJ10(IO_L22P_T3U_N6_DBC_AD0P_66) ; also on sheet 65 66 67 68
PL_DDR4_C0_BA0: U1.AM7(IO_L10N_T1U_N7_QBC_AD4N_66) ; also on sheet 65 66 67 68
PL_DDR4_C0_BA1: U1.AM8(IO_L10P_T1U_N6_QBC_AD4P_66) ; also on sheet 65 66 67 68
PL_DDR4_C0_BG0: U1.AG9(IO_L21N_T3L_N5_AD8N_66) ; also on sheet 65 66 67 68
PL_DDR4_C0_BG1: U1.AG10(IO_L21P_T3L_N4_AD8P_66) ; also on sheet 65 66 67 68
PL_DDR4_C0_CAS_B: U1.AF11(IO_L23N_T3U_N9_66) ; also on sheet 65 66 67 68
PL_DDR4_C0_CK0_C: U1.AM9(IO_L13N_T2L_N1_GC_QBC_66) ; also on sheet 65 66 67 68
PL_DDR4_C0_CK0_T: U1.AL9(IO_L13P_T2L_N0_GC_QBC_66) ; also on sheet 65 66 67 68
PL_DDR4_C0_CKE: U1.AF10(IO_L24N_T3U_N11_66) ; also on sheet 65 66 67 68
PL_DDR4_C0_CS1_B: U1.AF12(IO_L23P_T3U_N8_66) ; also on sheet 67 68
PL_DDR4_C0_CS2_B: U1.AM6(IO_L3P_T0L_N4_AD15P_66) ; also on sheet 65 66
PL_DDR4_C0_DM0_B: U1.AH13(IO_L7P_T1L_N0_QBC_AD13P_65) ; also on sheet 65
PL_DDR4_C0_DM1_B: U1.AM14(IO_L1P_T0L_N0_DBC_65) ; also on sheet 66
PL_DDR4_C0_DM2_B: U1.AC13(IO_L19P_T3L_N0_DBC_AD9P_65) ; also on sheet 67
PL_DDR4_C0_DM3_B: U1.AG15(IO_L13P_T2L_N0_GC_QBC_65) ; also on sheet 68
PL_DDR4_C0_DQ0: U1.AK14(IO_L8N_T1L_N3_AD5N_65) ; also on sheet 65
PL_DDR4_C0_DQ1: U1.AJ16(IO_L11P_T1U_N8_GC_65) ; also on sheet 65
PL_DDR4_C0_DQ2: U1.AJ15(IO_L11N_T1U_N9_GC_65) ; also on sheet 65
PL_DDR4_C0_DQ3: U1.AJ17(IO_L12P_T1U_N10_GC_65) ; also on sheet 65
PL_DDR4_C0_DQ4: U1.AK16(IO_L12N_T1U_N11_GC_65) ; also on sheet 65
PL_DDR4_C0_DQ5: U1.AK18(IO_L9P_T1L_N4_AD12P_65) ; also on sheet 65
PL_DDR4_C0_DQ6: U1.AK15(IO_L8P_T1L_N2_AD5P_65) ; also on sheet 65
PL_DDR4_C0_DQ7: U1.AL18(IO_L9N_T1L_N5_AD12N_65) ; also on sheet 65
PL_DDR4_C0_DQ8: U1.AN18(IO_L6P_T0U_N10_AD6P_65) ; also on sheet 66
PL_DDR4_C0_DQ9: U1.AP16(IO_L3P_T0L_N4_AD15P_65) ; also on sheet 66
PL_DDR4_C0_DQ10: U1.AM17(IO_L5P_T0U_N8_AD14P_65) ; also on sheet 66
PL_DDR4_C0_DQ11: U1.AP15(IO_L3N_T0L_N5_AD15N_65) ; also on sheet 66
PL_DDR4_C0_DQ12: U1.AN17(IO_L5N_T0U_N9_AD14N_65) ; also on sheet 66
PL_DDR4_C0_DQ13: U1.AN15(IO_L2N_T0L_N3_65) ; also on sheet 66
PL_DDR4_C0_DQ14: U1.AP17(IO_L6N_T0U_N11_AD6N_65) ; also on sheet 66
PL_DDR4_C0_DQ15: U1.AM15(IO_L2P_T0L_N2_65) ; also on sheet 66
PL_DDR4_C0_DQ16: U1.AE18(IO_L24N_T3U_N11_PERSTN0_65) ; also on sheet 67
PL_DDR4_C0_DQ17: U1.AE15(IO_L21N_T3L_N5_AD8N_65) ; also on sheet 67
PL_DDR4_C0_DQ18: U1.AE14(IO_L20P_T3L_N2_AD1P_65) ; also on sheet 67
PL_DDR4_C0_DQ19: U1.AD15(IO_L21P_T3L_N4_AD8P_65) ; also on sheet 67
PL_DDR4_C0_DQ20: U1.AD18(IO_L24P_T3U_N10_PERSTN1_I2C_SDA_65) ; also on sheet 67
PL_DDR4_C0_DQ21: U1.AD16(IO_L23N_T3U_N9_65) ; also on sheet 67
PL_DDR4_C0_DQ22: U1.AE13(IO_L20N_T3L_N3_AD1N_65) ; also on sheet 67
PL_DDR4_C0_DQ23: U1.AC17(IO_L23P_T3U_N8_I2C_SCLK_65) ; also on sheet 67
PL_DDR4_C0_DQ24: U1.AF16(IO_L17N_T2U_N9_AD10N_65) ; also on sheet 68
PL_DDR4_C0_DQ25: U1.AF13(IO_L15N_T2L_N5_AD11N_65) ; also on sheet 68
PL_DDR4_C0_DQ26: U1.AG17(IO_L14P_T2L_N2_GC_65) ; also on sheet 68
PL_DDR4_C0_DQ27: U1.AF14(IO_L15P_T2L_N4_AD11P_65) ; also on sheet 68
PL_DDR4_C0_DQ28: U1.AE16(IO_L17P_T2U_N8_AD10P_65) ; also on sheet 68
PL_DDR4_C0_DQ29: U1.AF18(IO_L18P_T2U_N10_AD2P_65) ; also on sheet 68
PL_DDR4_C0_DQ30: U1.AH17(IO_L14N_T2L_N3_GC_65) ; also on sheet 68
PL_DDR4_C0_DQ31: U1.AF17(IO_L18N_T2U_N11_AD2N_65) ; also on sheet 68
PL_DDR4_C0_DQS0_C: U1.AJ18(IO_L10N_T1U_N7_QBC_AD4N_65) ; also on sheet 65
PL_DDR4_C0_DQS0_T: U1.AH18(IO_L10P_T1U_N6_QBC_AD4P_65) ; also on sheet 65
PL_DDR4_C0_DQS1_C: U1.AM16(IO_L4N_T0U_N7_DBC_AD7N_65) ; also on sheet 66
PL_DDR4_C0_DQS1_T: U1.AL17(IO_L4P_T0U_N6_DBC_AD7P_SMBALERT_65) ; also on sheet 66
PL_DDR4_C0_DQS2_C: U1.AC15(IO_L22N_T3U_N7_DBC_AD0N_65) ; also on sheet 67
PL_DDR4_C0_DQS2_T: U1.AC16(IO_L22P_T3U_N6_DBC_AD0P_65) ; also on sheet 67
PL_DDR4_C0_DQS3_C: U1.AH14(IO_L16N_T2U_N7_QBC_AD3N_65) ; also on sheet 68
PL_DDR4_C0_DQS3_T: U1.AG14(IO_L16P_T2U_N6_QBC_AD3P_65) ; also on sheet 68
PL_DDR4_C0_ODT: U1.AH10(IO_L20P_T3L_N2_AD1P_66) ; also on sheet 65 66 67 68
PL_DDR4_C0_PARITY: U1.AH12(IO_T3U_N12_66) ; also on sheet 65 66 67 68
PL_DDR4_C0_RAS_B: U1.AG11(IO_L19N_T3L_N1_DBC_AD9N_66) ; also on sheet 65 66 67 68
PL_DDR4_C0_RESET_B: U1.AE11(IO_L24P_T3U_N10_66) ; also on sheet 65 66 67 68
PL_DDR4_C0_WE_B: U1.AJ9(IO_L22N_T3U_N7_DBC_AD0N_66) ; also on sheet 65 66 67 68
RSV_U1_AN14: U1.AN14(IO_L1N_T0L_N1_DBC_65)
RSV_U1_J20: U1.J20(VREF_67)
SFP0_RX_N: U1.P34(MGTYRXN0_127) ; also on sheet 33
SFP0_RX_P: U1.P33(MGTYRXP0_127) ; also on sheet 33
SFP0_TX_N: U1.N31(MGTYTXN0_127) ; also on sheet 33
SFP0_TX_P: U1.N30(MGTYTXP0_127) ; also on sheet 33
SFP1_RX_N: U1.M34(MGTYRXN1_127) ; also on sheet 33
SFP1_RX_P: U1.M33(MGTYRXP1_127) ; also on sheet 33
SFP1_TX_N: U1.L31(MGTYTXN1_127) ; also on sheet 33
SFP1_TX_P: U1.L30(MGTYTXP1_127) ; also on sheet 33
SFP2_RX_N: U1.K34(MGTYRXN2_127) ; also on sheet 33
SFP2_RX_P: U1.K33(MGTYRXP2_127) ; also on sheet 33
SFP2_TX_N: U1.J31(MGTYTXN2_127) ; also on sheet 33
SFP2_TX_P: U1.J30(MGTYTXP2_127) ; also on sheet 33
SFP3_RX_N: U1.H34(MGTYRXN3_127) ; also on sheet 33
SFP3_RX_P: U1.H33(MGTYRXP3_127) ; also on sheet 33
SFP3_TX_N: U1.G31(MGTYTXN3_127) ; also on sheet 33
SFP3_TX_P: U1.G30(MGTYTXP3_127) ; also on sheet 33
SI5381_ADC_REFCLK_N: U1.AD4(ADC_CLK_N_225) ; also on sheet 36
SI5381_ADC_REFCLK_P: U1.AD5(ADC_CLK_P_225) ; also on sheet 36
SI5381_CLK2_IN_C_N: C1518.1 U1.A12(IO_L10N_T1U_N7_QBC_AD4N_67)
SI5381_CLK2_IN_C_P: C1519.1 U1.B12(IO_L10P_T1U_N6_QBC_AD4P_67)
SI5381_CLK2_IN_N: C1518.2 ; also on sheet 36
SI5381_CLK2_IN_P: C1519.2 ; also on sheet 36
SI5381_CLK104_MUX_SEL: U1.K10(IO_L10N_AD2N_88) ; also on sheet 39
SI5381_CLK_125_N: R9.2 U1.D14(IO_L11N_T1U_N9_GC_67) ; also on sheet 36
SI5381_CLK_125_P: R9.1 U1.E14(IO_L11P_T1U_N8_GC_67) ; also on sheet 36
SI5381_DAC_REFCLK_N: U1.L4(DAC_CLK_N_227) ; also on sheet 36
SI5381_DAC_REFCLK_P: U1.L5(DAC_CLK_P_227) ; also on sheet 36
SI5381_PL_CLK_N: R919.2 R1034.2 R1036.1 U1.AP10(IO_L11N_T1U_N9_GC_66) ; also on sheet 36
SI5381_PL_CLK_P: R919.1 R1033.2 R1035.1 U1.AP11(IO_L11P_T1U_N8_GC_66) ; also on sheet 36
SI53340_MUX_GT_SEL: U1.K11(IO_L10P_AD2P_88) ; also on sheet 38
SI53340_MUX_GTR_SEL: U1.H9(IO_L9N_AD3N_88) ; also on sheet 12
SYSMON_AGND: C1.2 C2.2 C3.2 C4.2 C5.2 J4.3(P3) J5.5(P5) J5.6(P6) L2.1 U1.R15(GNDADC) U1.T14(VREFN) U2.3(GND)
SYSMON_DXN: J5.4(P4) U1.V14(DXN) ; also on sheet 43
SYSMON_DXP: J5.2(P2) U1.V15(DXP) ; also on sheet 43
SYSMON_SCL_LS: U1.J12(IO_L12N_AD0N_88) ; also on sheet 22
SYSMON_SDA_LS: U1.K12(IO_L12P_AD0P_88) ; also on sheet 22
SYSMON_VN: J5.9(P9) R8.2
SYSMON_VN_R: C6.2 J3.1(P1) R8.1 U1.U14(VN)
SYSMON_VN_R_I2C: J3.2(P2) R6.1
SYSMON_VP: J5.10(P10) R7.2
SYSMON_VP_R: C6.1 J2.1(P1) R7.1 U1.T15(VP)
SYSMON_VP_R_I2C: J2.2(P2) R3.2 R4.1
SYSMON_VREF: C5.1 J4.1(P1) J5.7(P7) U2.2(OUT)
SYSMON_VREFP: C3.1 J4.2(P2) U1.U15(VREFP)
TDD_TRIGGER_IN: R1751.1 U1.K20(IO_T1U_N12_67)
TDD_TRIGGER_OUT: R1752.1 U1.H10(IO_L9P_AD3P_88)
UART0_RXD_MIO19_TXD: U1.C16(PS_MIO19) ; also on sheet 25
UART0_TXD_MIO18_RXD: U1.F18(PS_MIO18) ; also on sheet 25
UART2_CTS_B: U1.AD17(IO_T3U_N12_65) ; also on sheet 25
UART2_RTS_B: U1.AD13(IO_L19N_T3L_N1_DBC_AD9N_65) ; also on sheet 25
UART2_RXD_FPGA_TXD: U1.AG16(IO_T2U_N12_65) ; also on sheet 25
UART2_TXD_FPGA_RXD: U1.AH15(IO_L13N_T2L_N1_GC_QBC_65) ; also on sheet 25
USER_MGT_REFCLK_C_N: C16.1 U1.K29(MGTREFCLK1N_127)
USER_MGT_REFCLK_C_P: C15.1 U1.K28(MGTREFCLK1P_127)
USER_MGT_REFCLK_N: C16.2 ; also on sheet 38
USER_MGT_REFCLK_P: C15.2 ; also on sheet 38
USER_SI570_C0_N: R1097.2 U1.AN10(IO_L12N_T1U_N11_GC_66) ; also on sheet 42
USER_SI570_C0_P: R1097.1 U1.AM10(IO_L12P_T1U_N10_GC_66) ; also on sheet 42
UTIL_3V3: DS1.2 ; also on sheet 10 20 22 23 24 25 26 27 28 29 30 31 33 34 36 37 40 42 43 44 45 47 49 51 53 54 55 56 57 59 60 61 64
VCM01_224: U1.AJ5(VCM01_224) ; also on sheet 61
VCM01_225: U1.AH5(VCM01_225) ; also on sheet 61
VCM01A_AF5_226: U1.AF5(VCM01A_226) ; also on sheet 61
VCM01B_AG5_226: U1.AG5(VCM01B_226) ; also on sheet 61
VCM23_224: U1.AJ4(VCM23_224) ; also on sheet 61
VCM23_225: U1.AH4(VCM23_225) ; also on sheet 61
VCM23A_AF4_226: U1.AF4(VCM23A_226) ; also on sheet 61
VCM23B_AG4_226: U1.AG4(VCM23B_226) ; also on sheet 61
VREF_65: R11.1 U1.AC14(VREF_65)
VREF_66: R12.1 U1.AE10(VREF_66)
VRP_65: R14.1 U1.AL14(IO_T0U_N12_VRP_65)
VRP_66: R17.1 U1.AN3(IO_T0U_N12_VRP_66)
VRP_67: R18.1 U1.L20(IO_T0U_N12_VRP_67)
N16942408: J1.2(P2) R5.1 U1.AD11(POR_OVERRIDE)
N16943469: R1.2 R2.1 U1.AC12(PUDC_B)
N20238874: R26.1 U1.F6(DAC_REXT_227)
N21036355: R33.2 SW1.1(P1) SW1.2(P2)
N21036552: Q1.3(DRAIN) R34.2
N29170585: R25.1 U1.AF7(ADC_REXT_224)
N30565844: J144.1(SIG) R1751.2
N30565907: J145.1(SIG) R1752.2
N33717569: DS1.1 R34.1

Not connected (* = marked no-connect by the designer): J5 1(P1)* 3(P3)*; U1 A17(PS_MIO24) B16(PS_MIO20) B17(PS_MIO25) C20(PS_MIO44) F17(PS_MIO21) G20(PS_MIO31) H16(PS_MIO6)

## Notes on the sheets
sheet 1
- RFSoC UltraScale+ Evaluation Board
- HW-Z2-ZCU670
- NOTICE:  These schematics are made available for users who are working with this specific Xilinx board and should
  not be considered an optimal board design reference.  This board was designed for evaluation purposes with
  components that are potentially more complex and costly than would be used in an end customer system.  Users are
  encouraged to leverage the Xilinx design guidelines as the optimal starting point for new board designs.
  © Copyright 2020 Xilinx, Inc. Xilinx, the Xilinx logo, Artix, ISE, Kintex, Spartan, Virtex, Zynq, and other designated
  brands included herein are trademarks of Xilinx in the United States and other countries. [If applicable, insert
  relevant third-party sentence.] All other trademarks are the property of their respective owners.
  DISCLAIMER The information disclosed to you hereunder (the “Materials”) is provided solely for the selection and use
  of Xilinx products. To the maximum extent permitted by applicable law: (1) Materials are made available "AS IS" and with
  all faults, Xilinx hereby DISCLAIMS ALL WARRANTIES AND CONDITIONS, EXPRESS, IMPLIED, OR STATUTORY, INCLUDING BUT NOT LIMITED TO
  WARRANTIES OF MERCHANTABILITY, NON-INFRINGEMENT, OR FITNESS FOR ANY PARTICULAR PURPOSE; and (2) Xilinx shall not be
  liable (whether in contract or tort, including negligence, or under any other theory of liability) for any loss or
  damage of any kind or nature related to, arising under, or in connection with, the Materials (including your use of
  the Materials), including for any direct, indirect, special, incidental, or consequential loss or damage (including loss
  of data, profits, goodwill, or any type of loss or damage suffered as a result of any
  action brought by a third party) even if such damage or loss was reasonably foreseeable or Xilinx had been advised of
  the possibility of the same. Xilinx assumes no obligation to correct any errors contained in the Materials or to notify you
  of updates to the Materials or to product specifications. You may not reproduce, modify, distribute, or publicly display the
  Materials without prior written consent. Certain products are subject to the terms and conditions of Xilinx’s limited
  warranty, please refer to Xilinx’s Terms of Sale which can be viewed at http://www.xilinx.com/legal.htm#tos; IP cores
  may be subject to warranty and support terms contained in a license issued to you by Xilinx. Xilinx products are not designed
  or intended to be fail-safe or for use in any application requiring fail-safe performance; you assume sole risk
  and liability for use of Xilinx products in such critical applications, please refer to Xilinx’s Terms of Sale which can be
  viewed at http://www.xilinx.com/legal.htm#tos.
sheet 2
- Default jumper location indicator:
sheet 3
- POR_OVERRIDE select
- Default: 2-3 GND
- SYSMON I2C Address jumpers
sheet 5
- ZU47DR device:
  K20/L20/J20 are SDFEC power pins
sheet 6
- ==> 1588
- <== CLK MUX
- ==> 1588
- <== 1588
- Equal in length
sheet 8
- 0 ohms for DC connection
